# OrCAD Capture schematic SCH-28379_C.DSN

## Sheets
1 4. OpenSDA interface: size D; title: X-FRDM-KW40Z; rev: C; company: Freescale Semiconductor; note: SCH-28379 | PDF: SPF-28379; note: 6501 William Cannon Drive West; note: Austin, TX 78735-8598
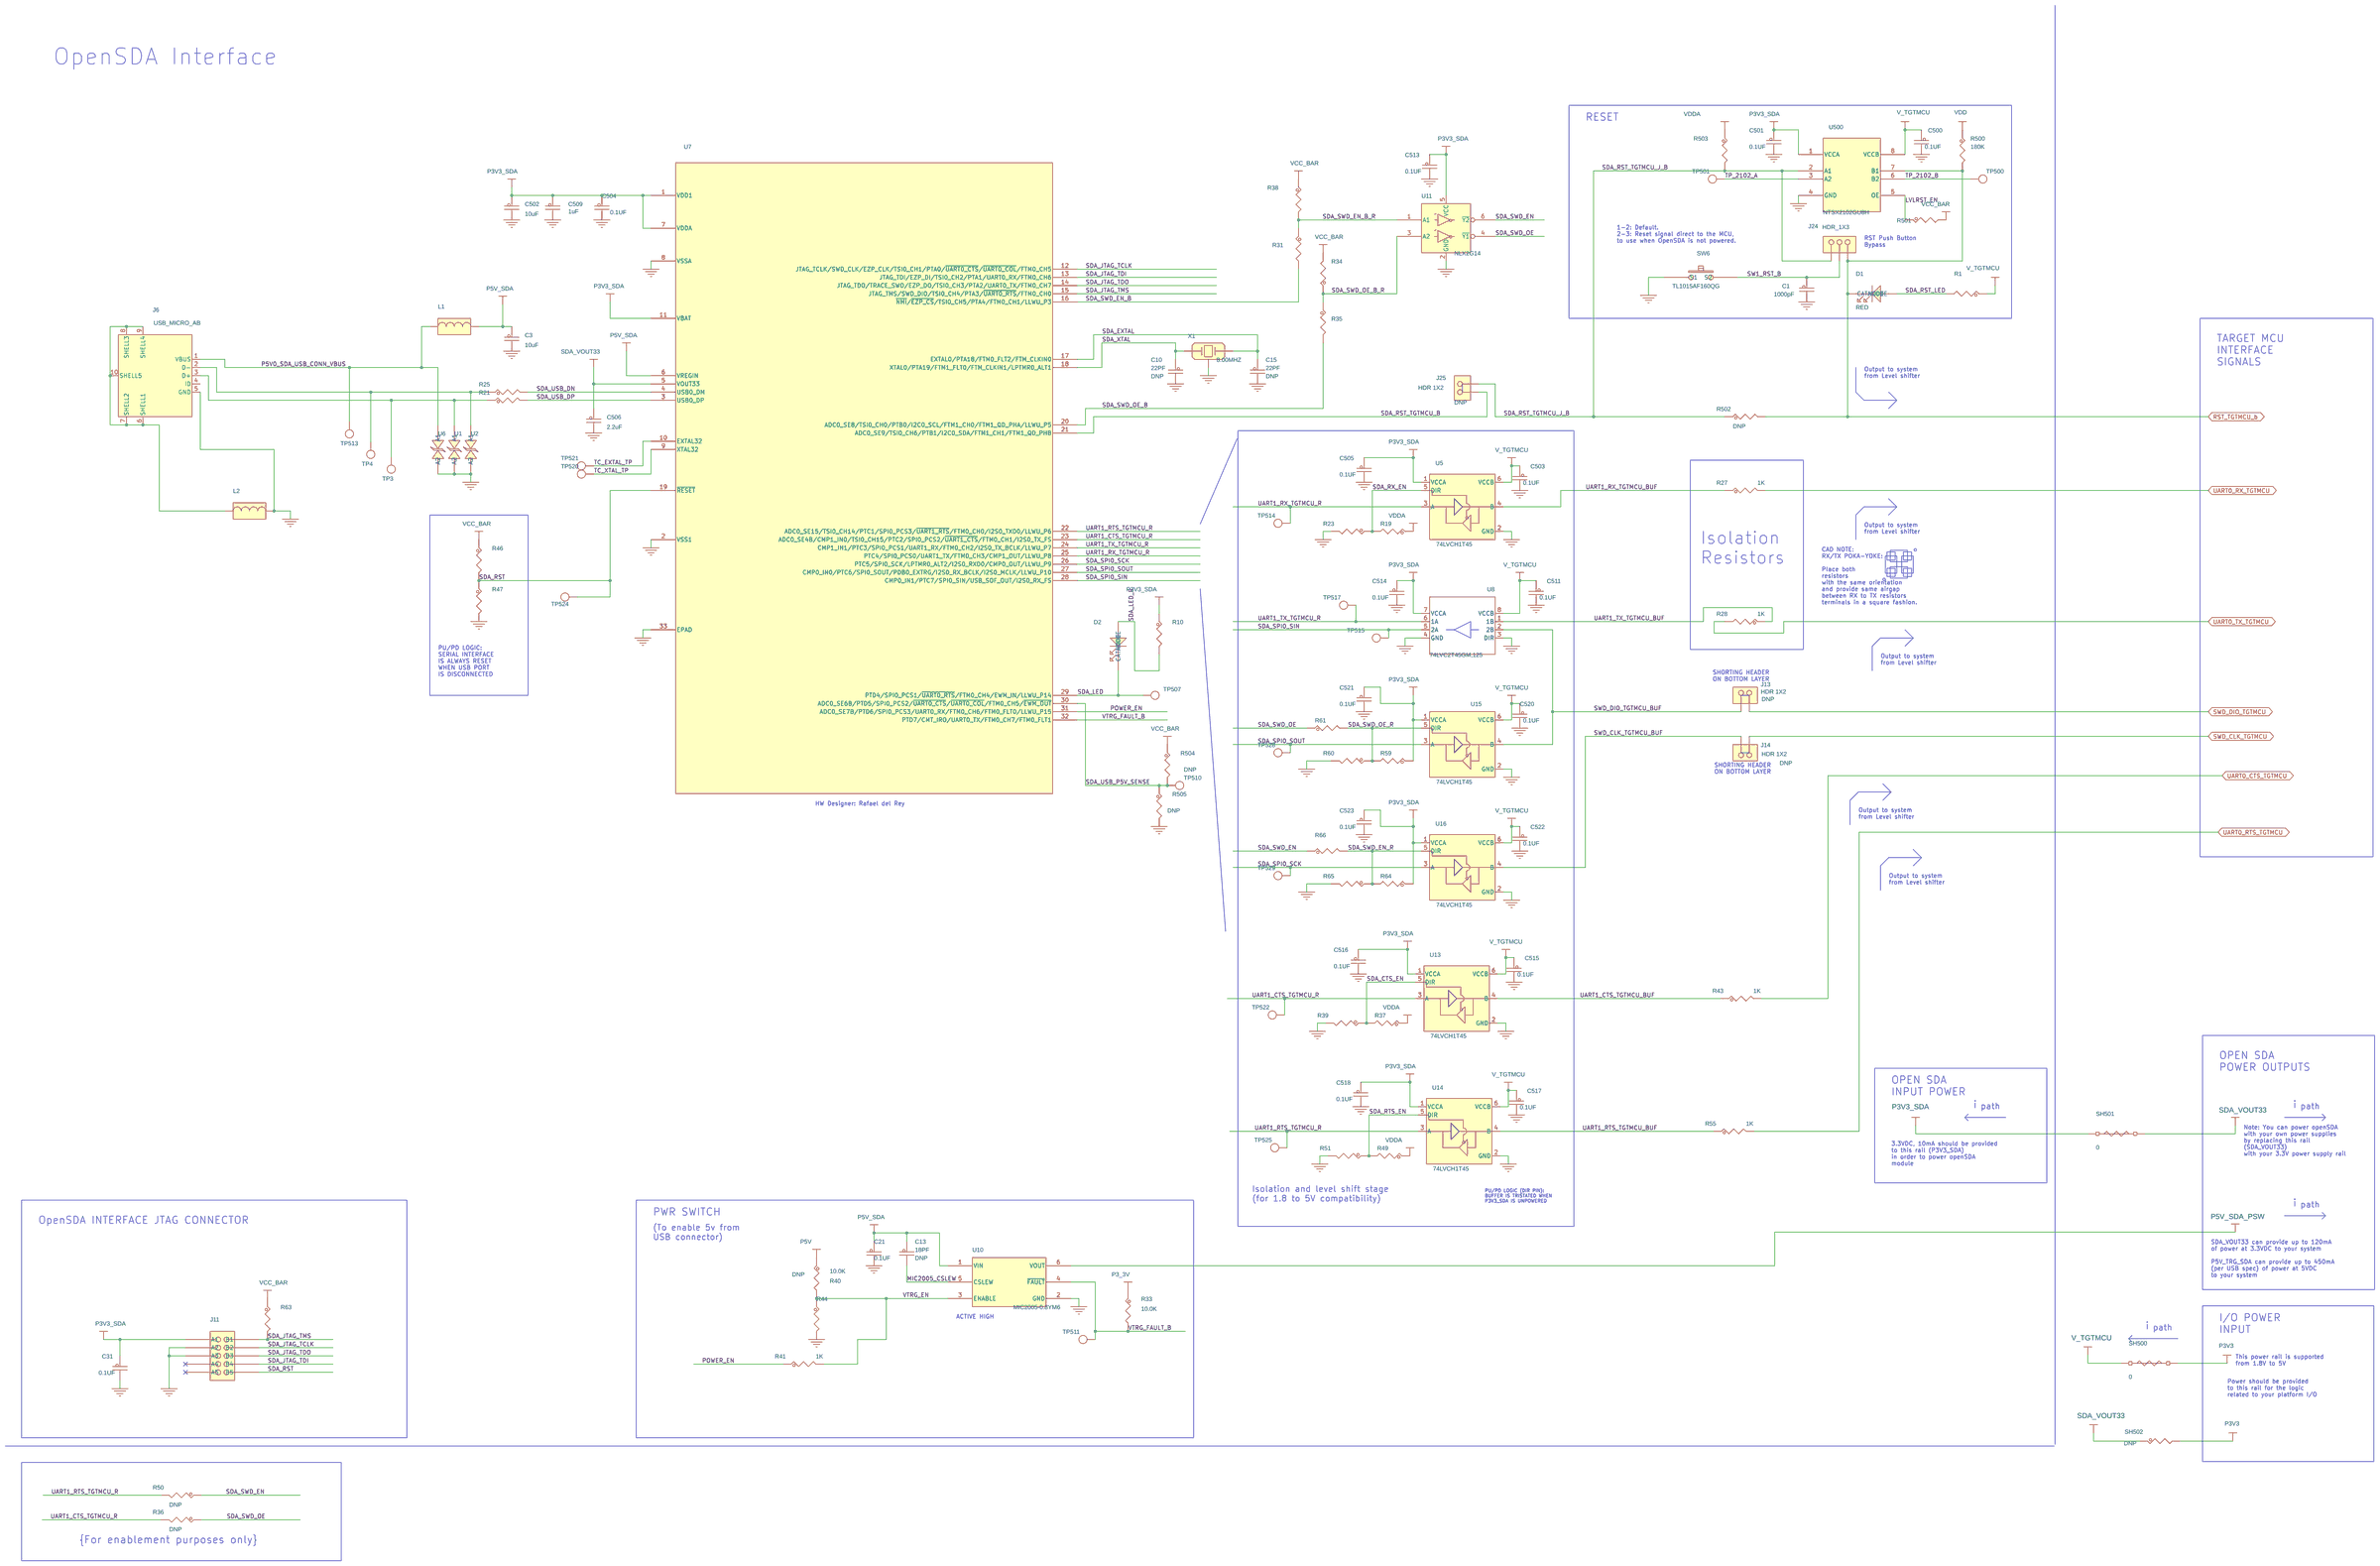
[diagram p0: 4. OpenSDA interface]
2 3. MKW40Z MCU: size C
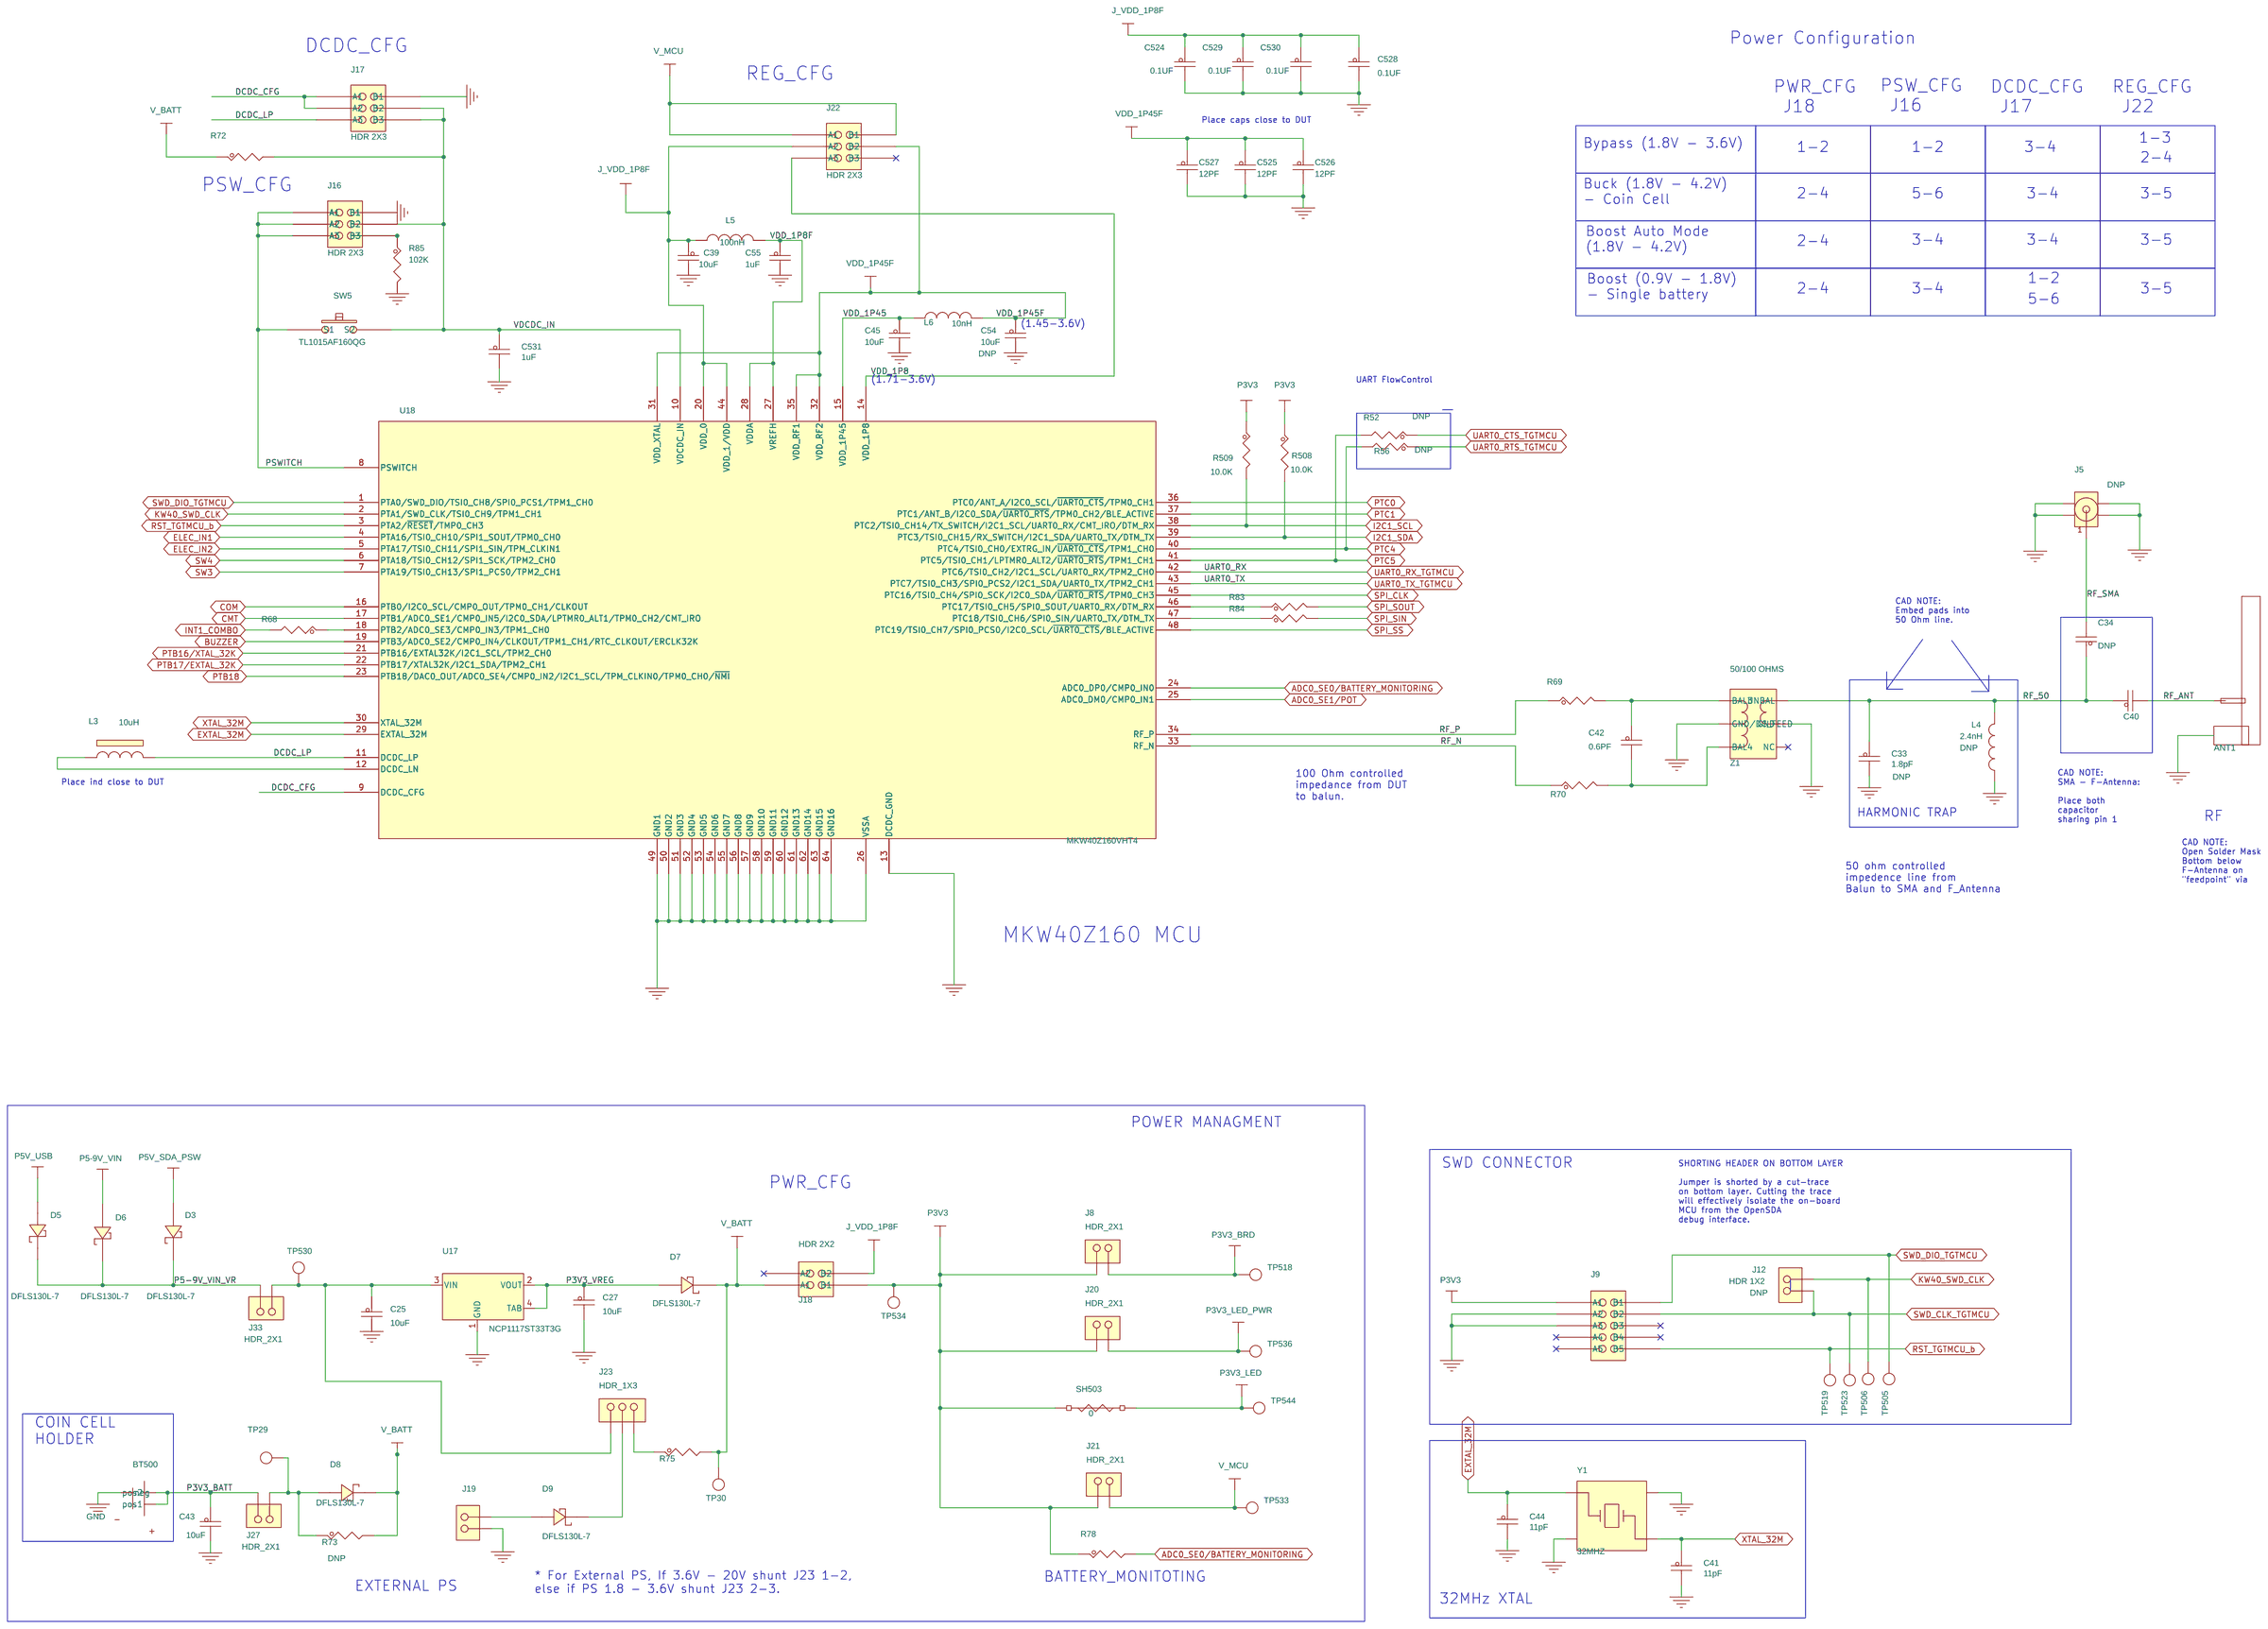
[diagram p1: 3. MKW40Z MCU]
3 2. Block Diagram
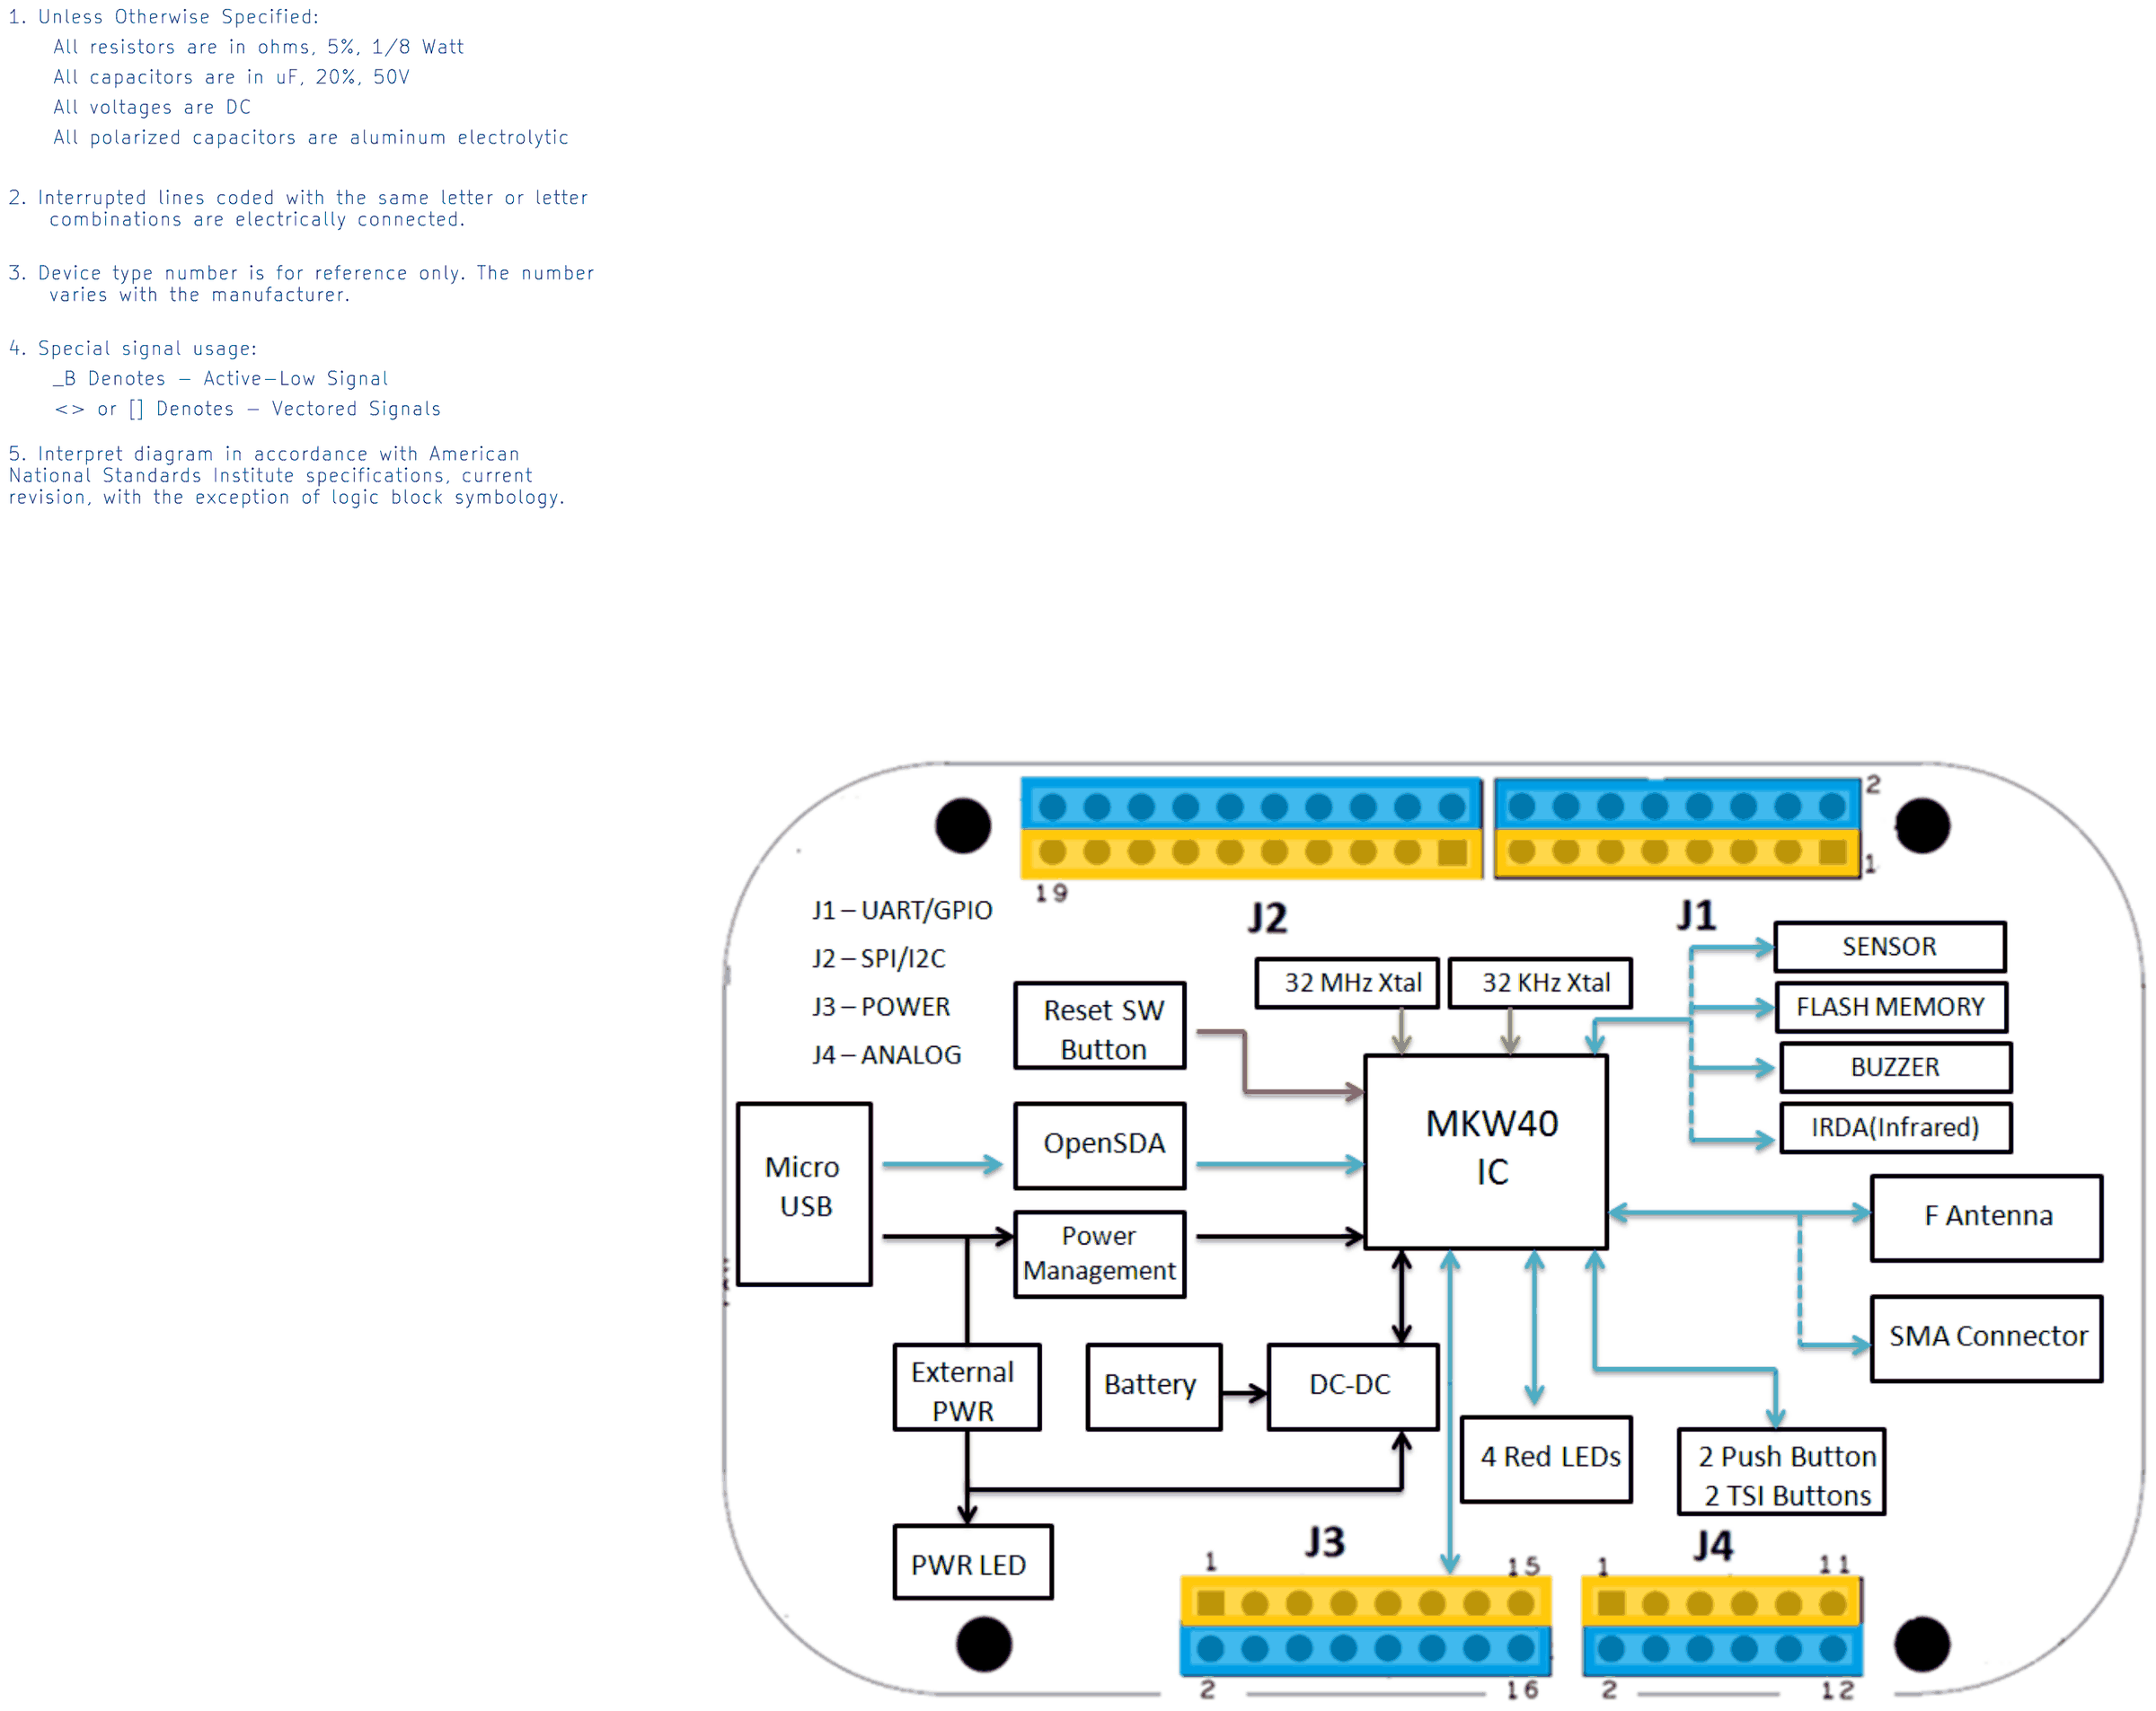
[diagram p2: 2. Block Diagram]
4 1. Title Page
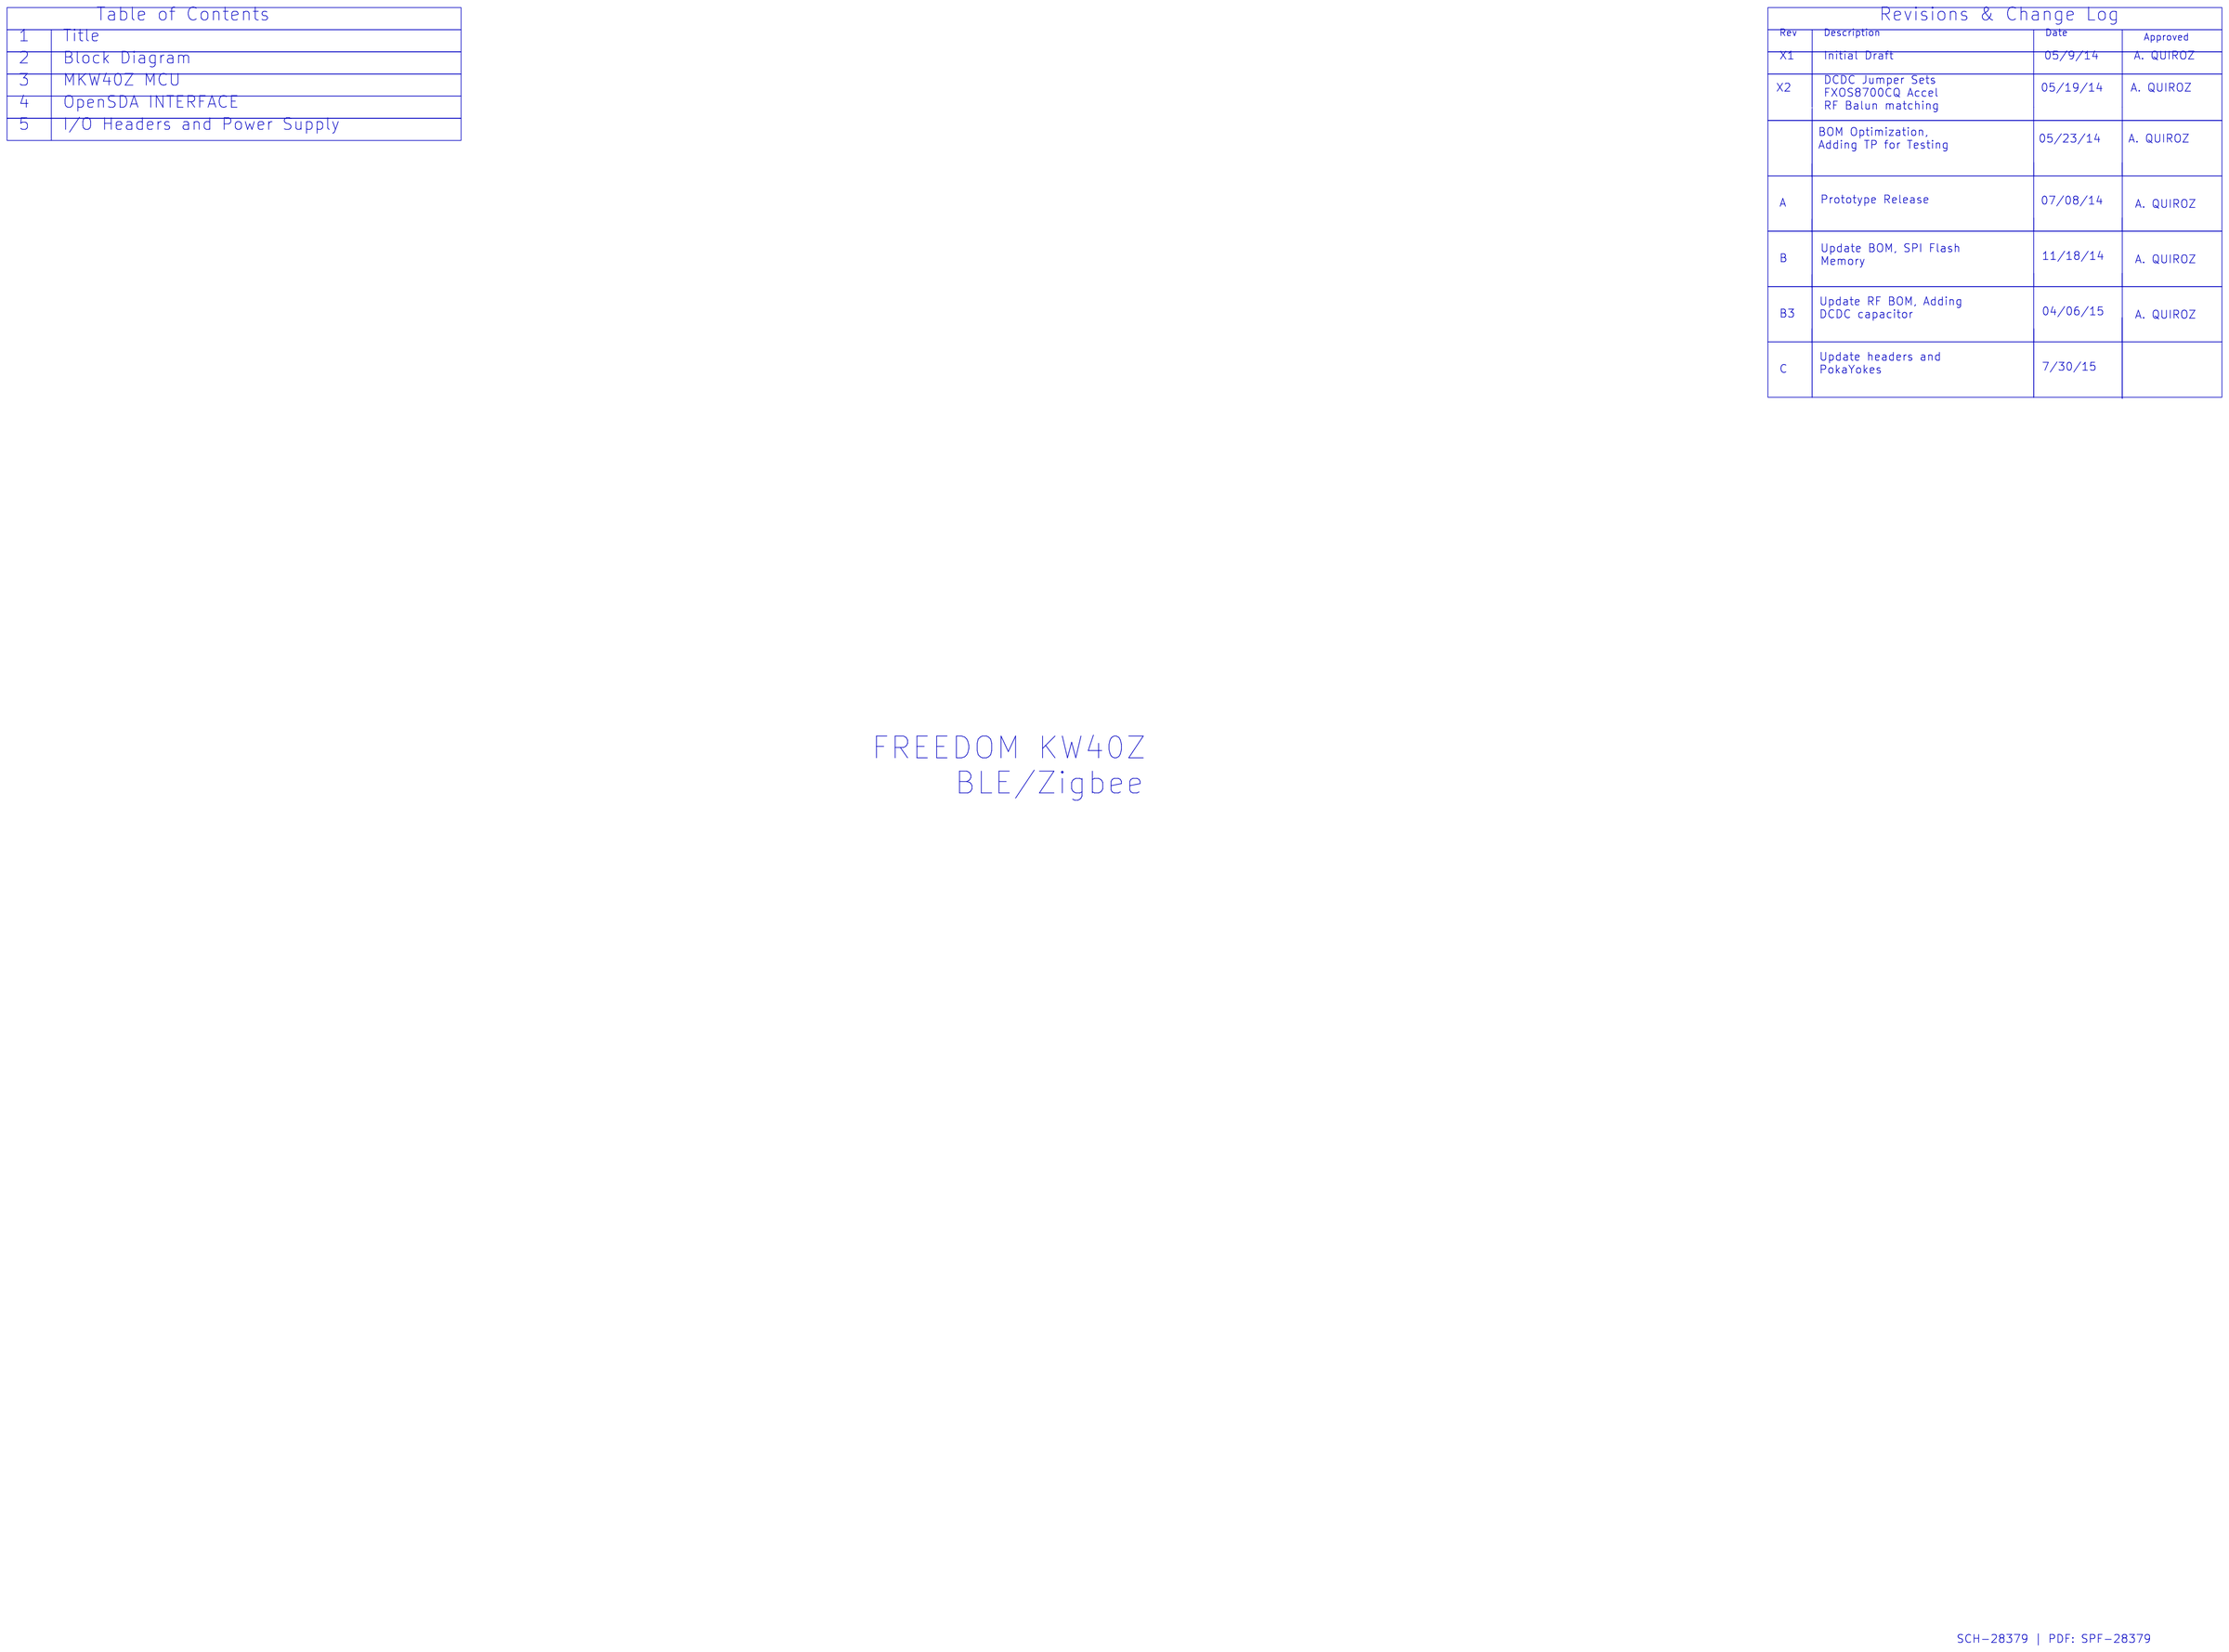
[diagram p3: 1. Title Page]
5 5. I/O Headers and Power Supply: size C
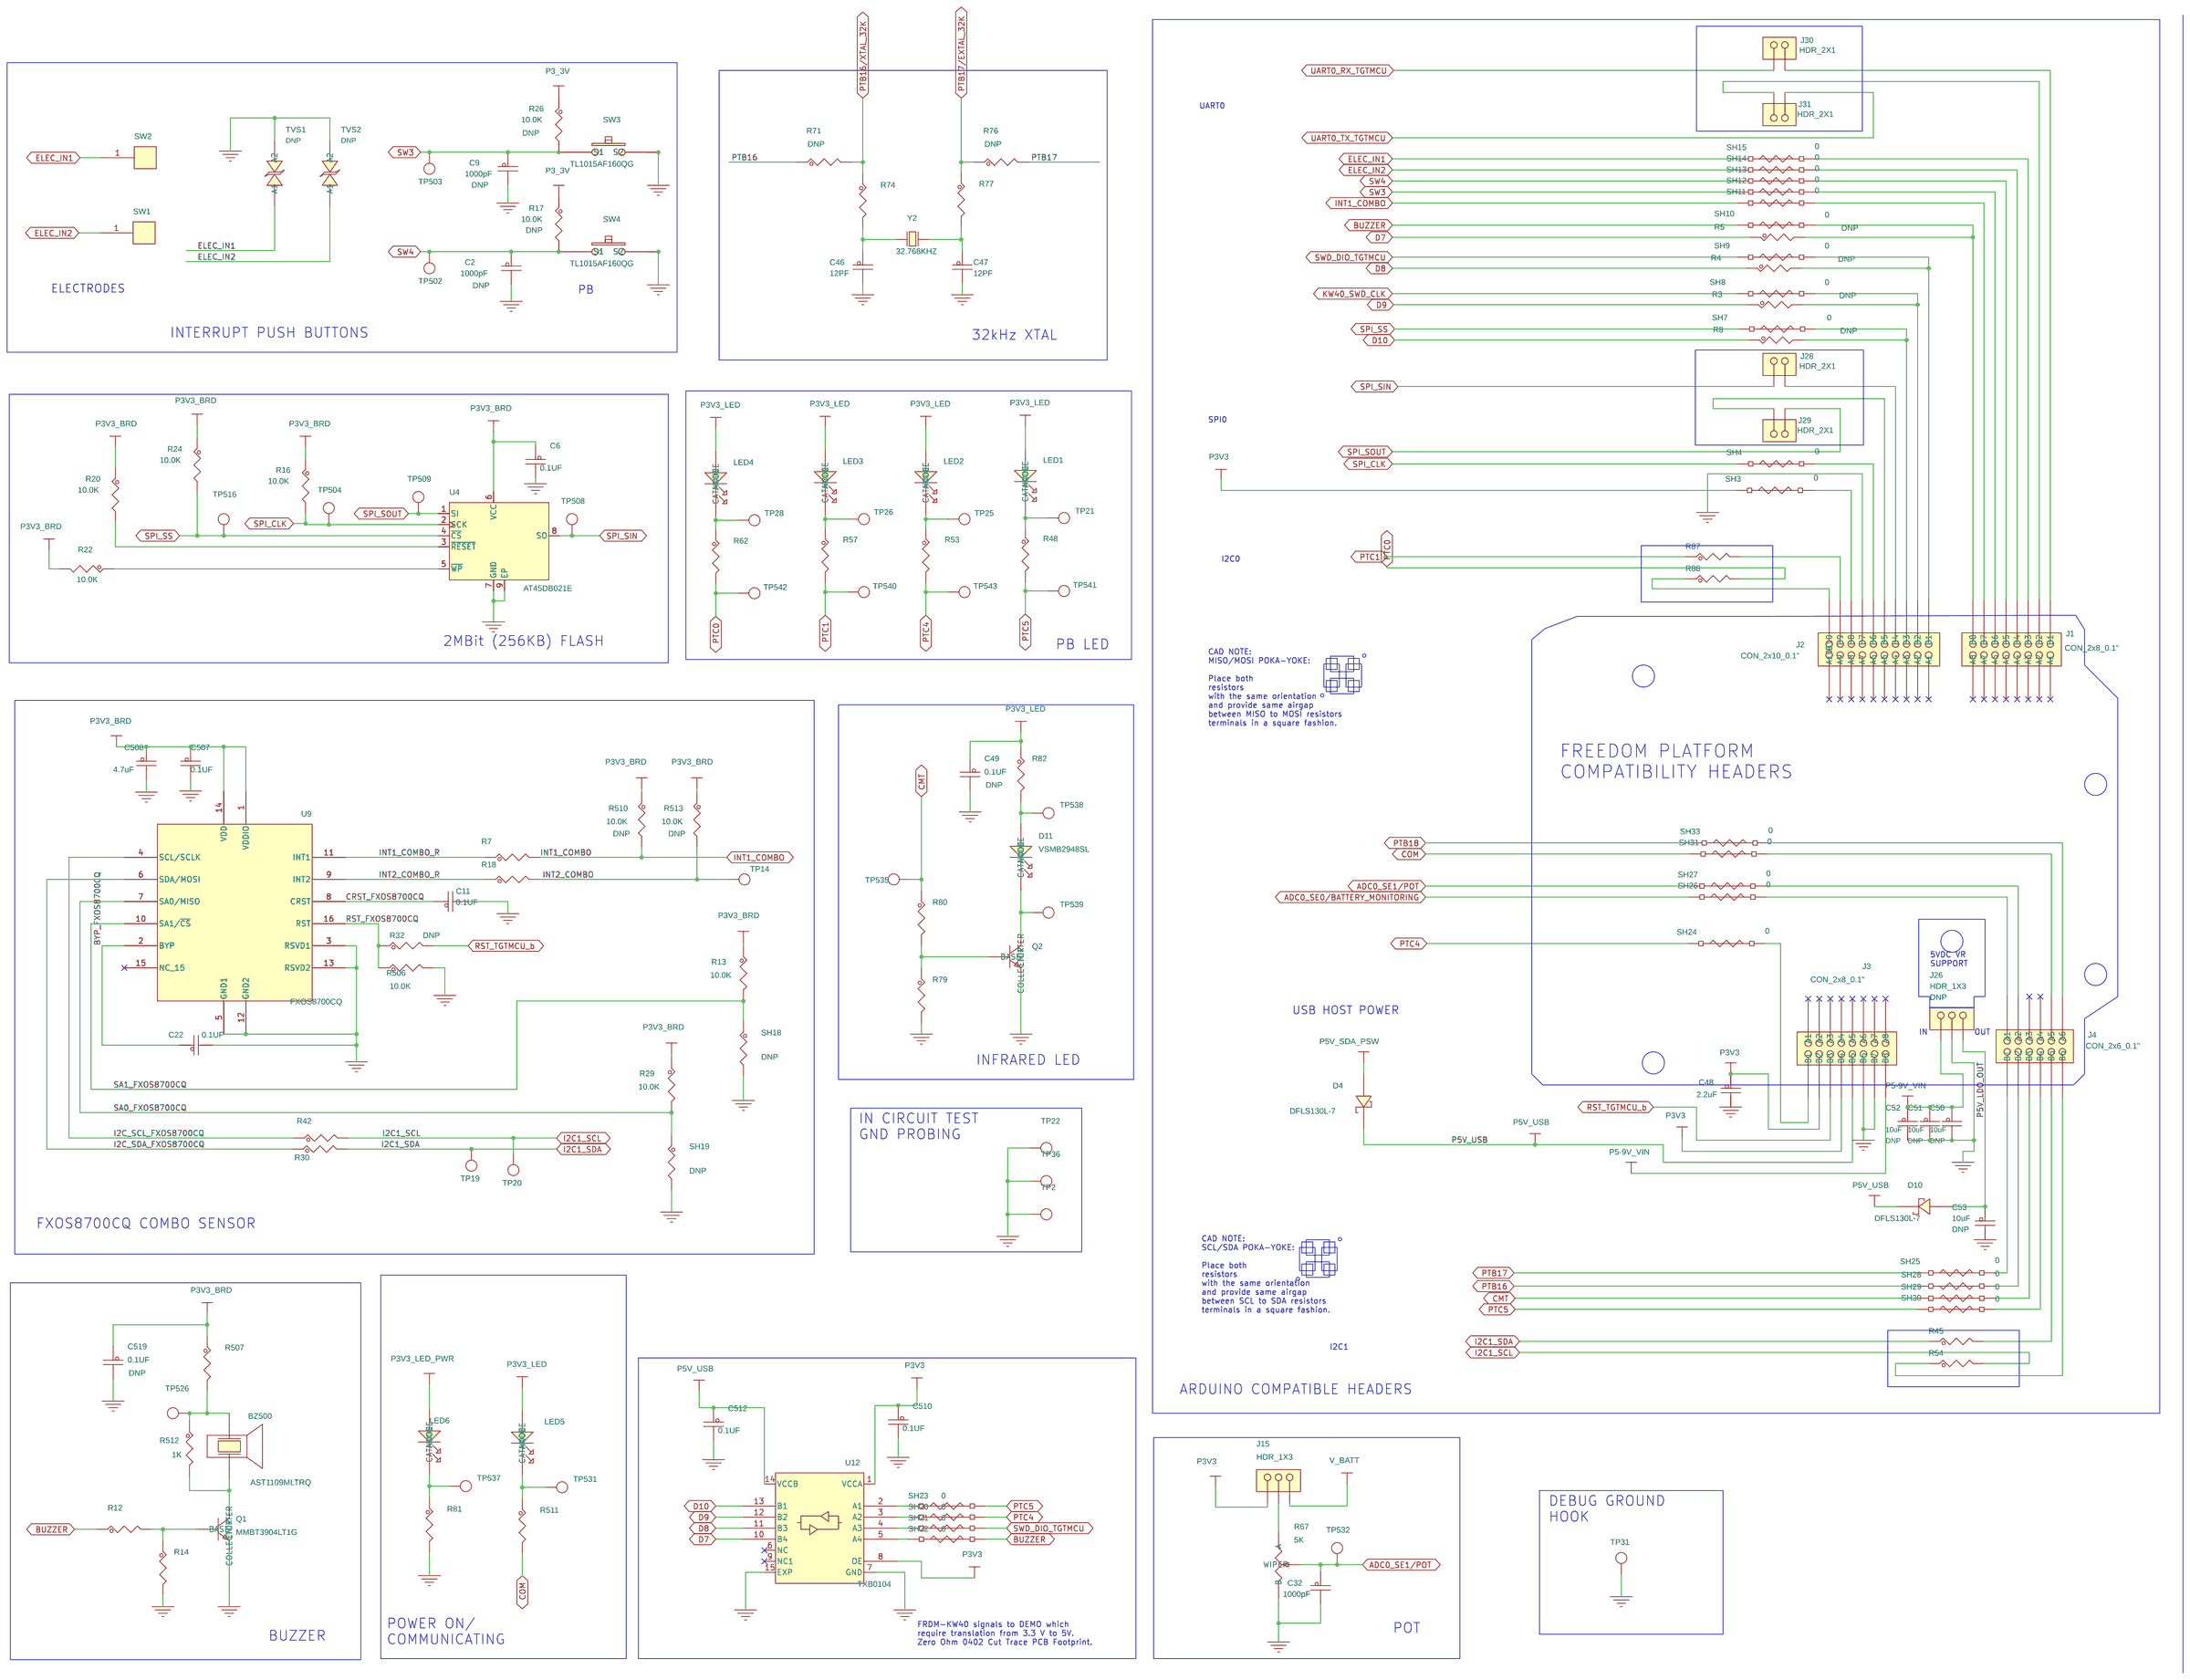
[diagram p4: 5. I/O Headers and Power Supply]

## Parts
sheet 3. MKW40Z MCU
ANT1  F_Antenna  [f_antenna_dig528-2]
BT500  3003  [batt_21x20mm]
C25  10uF  [CC0603_OV]
C27  10uF  [CC0603_OV]
C33  1.8pF  [CC0402_25]
C34  10PF  [CC0402_25]
C39  10uF  [CC0603_OV]
C40  10PF  [CC0402_25]
C41  11pF  [CC0402_25]
C42  0.6PF  [CC0402_25]
C43  10uF  [CC0603_OV]
C44  11pF  [CC0402_25]
C45  10uF  [CC0603_OV]
C54  10uF  [CC0603_OV]
C55  1uF  [CC0603_OV]
C524  0.1UF  [CC0402_25]
C525  12PF  [CC0402_25]
C526  12PF  [CC0402_25]
C527  12PF  [CC0402_25]
C528  0.1UF  [CC0402_25]
C529  0.1UF  [CC0402_25]
C530  0.1UF  [CC0402_25]
C531  1uF  [CC0402_25]
D3  DFLS130L-7  [powerdi-123_3mmx2mm]
D5  DFLS130L-7  [powerdi-123_3mmx2mm]
D6  DFLS130L-7  [powerdi-123_3mmx2mm]
D7  DFLS130L-7  [powerdi-123_3mmx2mm]
D8  DFLS130L-7  [powerdi-123_3mmx2mm]
D9  DFLS130L-7  [powerdi-123_3mmx2mm]
J5  SMA  [CON_SMA_EDGE_062]
J8  HDR_2X1  [hdr102_2mm]
J9  HDR 2X5  [hdr_5X2_ftsh_th_nsp]
J12  HDR 1X2  [sh_hdr102_2mm_bottom]
J16  HDR 2X3  [hdr203_tmm]
J17  HDR 2X3  [hdr203_tmm]
J18  HDR 2X2  [hdr202_tmm]
J19  HDR 1X2 TH  [HDR102]
J20  HDR_2X1  [hdr102_2mm]
J21  HDR_2X1  [hdr102_2mm]
J22  HDR 2X3  [hdr203_tmm]
J23  HDR_1X3  [hdr103_78mil]
J27  HDR_2X1  [hdr102_2mm]
J33  HDR_2X1  [hdr102_2mm]
L3  10uH  [ind_vls4012e]
L4  2.4nH  [IND_0402]
L5  100nH  [IND_0402]
L6  10nH  [IND_0402]
R52  0  [RC0603_OV]
R56  0  [RC0603_OV]
R68  0  [RC0402_25]
R69  0  [RC0402_25]
R70  0  [RC0402_25]
R72  0  [RC0402_25]
R73  0  [RC0402_25]
R75  0  [RC0402_25]
R78  0  [RC0402_25]
R83  0  [RC0402_25]
R84  0  [RC0402_25]
R85  102K  [RC0402_25]
R508  10.0K  [RC0402_25]
R509  10.0K  [RC0402_25]
SH503  0  [SH0603]
SW5  TL1015AF160QG  [sw2_spst_4x3_sm]
TP29  TPAD_030  [TPAD_030]
TP30  TPAD_040  [TPAD_040]
TP505  TPAD_030  [TPAD_030]
TP506  TPAD_030  [TPAD_030]
TP518  TPAD_040  [TPAD_040]
TP519  TPAD_030  [TPAD_030]
TP523  TPAD_030  [TPAD_030]
TP530  TPAD_040  [TPAD_040]
TP533  TPAD_040  [TPAD_040]
TP534  TPAD_040  [TPAD_040]
TP536  TPAD_040  [TPAD_040]
TP544  TPAD_040  [TPAD_040]
U17  NCP1117ST33T3G  [sot223]
U18  MKW40Z160VHT4  [MAPLGA64_7X7_0P5MM]
Y1  32MHZ  [xtlosc4_3p2x2p5mm_sm]
Z1  50/100 OHMS  [xfmr6_0p65_2x1]
sheet 4. OpenSDA interface
C1  1000pF  [CC0402_25]
C3  10uF  [CC0603_OV]
C10  22PF  [CC0402_25]
C13  18PF  [CC0603_OV]
C15  22PF  [CC0402_25]
C21  0.1UF  [CC0402_25]
C31  0.1UF  [CC0402_25]
C500  0.1UF  [CC0402_25]
C501  0.1UF  [CC0402_25]
C502  10uF  [CC0603_OV]
C503  0.1UF  [CC0402_25]
C504  0.1UF  [CC0402_25]
C505  0.1UF  [CC0402_25]
C506  2.2uF  [CC0603_OV]
C509  1uF  [CC0402_25]
C511  0.1UF  [CC0402_25]
C513  0.1UF  [CC0402_25]
C514  0.1UF  [CC0402_25]
C515  0.1UF  [CC0402_25]
C516  0.1UF  [CC0402_25]
C517  0.1UF  [CC0402_25]
C518  0.1UF  [CC0402_25]
C520  0.1UF  [CC0402_25]
C521  0.1UF  [CC0402_25]
C522  0.1UF  [CC0402_25]
C523  0.1UF  [CC0402_25]
D1  RED  [LED_0603]
D2  LED GREEN  [LED_0603]
J6  USB_MICRO_AB  [con_microab_10f_25_sm_ra]
J11  HDR 2X5  [hdr_5X2_ftsh_th_nsp]
J13  HDR 1X2  [sh_hdr102_2mm_bottom]
J14  HDR 1X2  [sh_hdr102_2mm_bottom]
J24  HDR_1X3  [hdr103_78mil]
J25  HDR 1X2  [sh_hdr102_2mm_bottom]
L1  330 OHM  [ind_1608]
L2  330 OHM  [ind_1608]
R1  100  [RC0402_25]
R10  220  [RC0603_OV]
R19  4.7K  [RC0402_25]
R21  33  [RC0402_25]
R23  10.0K  [RC0402_25]
R25  33  [RC0402_25]
R27  1K  [RC0402_25]
R28  1K  [RC0402_25]
R31  0  [RC0402_25]
R33  10.0K  [RC0402_25]
R34  10.0K  [RC0402_25]
R35  0  [RC0402_25]
R36  0  [RC0402_25]
R37  4.7K  [RC0402_25]
R38  10.0K  [RC0402_25]
R39  10.0K  [RC0402_25]
R40  10.0K  [RC0402_25]
R41  1K  [RC0402_25]
R43  1K  [RC0402_25]
R44  15K  [RC0402_25]
R46  4.7K  [RC0402_25]
R47  10.0K  [RC0402_25]
R49  4.7K  [RC0402_25]
R50  0  [RC0402_25]
R51  10.0K  [RC0402_25]
R55  1K  [RC0402_25]
R59  4.7K  [RC0402_25]
R60  10.0K  [RC0402_25]
R61  0  [RC0402_25]
R63  10.0K  [RC0402_25]
R64  4.7K  [RC0402_25]
R65  10.0K  [RC0402_25]
R66  0  [RC0402_25]
R500  180K  [RC0402_25]
R501  4.7K  [RC0402_25]
R502  0  [RC0402_25]
R503  10.0K  [RC0402_25]
R504  4.7K  [RC0402_25]
R505  10.0K  [RC0402_25]
SH500  0  [SH0603]
SH501  0  [SH0603]
SH502  0  [RC0402_25]
SW6  TL1015AF160QG  [sw2_spst_4x3_sm]
TP3  TPAD_040  [TPAD_040]
TP4  TPAD_040  [TPAD_040]
TP500  TPAD_030  [TPAD_030]
TP501  TPAD_030  [TPAD_030]
TP507  TPAD_040  [TPAD_040]
TP510  TPAD_030  [TPAD_030]
TP511  TPAD_030  [TPAD_030]
TP513  TPAD_040  [TPAD_040]
TP514  TPAD_030  [TPAD_030]
TP515  TPAD_030  [TPAD_030]
TP517  TPAD_030  [TPAD_030]
TP520  TPAD_030  [TPAD_030]
TP521  TPAD_030  [TPAD_030]
TP522  TPAD_030  [TPAD_030]
TP524  TPAD_040  [TPAD_040]
TP525  TPAD_030  [TPAD_030]
TP528  TPAD_030  [TPAD_030]
TP529  TPAD_030  [TPAD_030]
U1  0402ESDA-MLP  [0402_mlp]
U2  0402ESDA-MLP  [0402_mlp]
U5  74LVCH1T45  [udfn6_1x1p5mm]
U6  0402ESDA-MLP  [0402_mlp]
U7  MK20DX128VFM5  [QFN32_S142EP]
U8  74LVC2T45GM,125  [qfn8_1p6x1p6mm]
U10  MIC2005-0.8YM6  [SOT23-6_a]
U11  NLX2G14  [UDFN6_1p45x1_0p5mm]
U13  74LVCH1T45  [udfn6_1x1p5mm]
U14  74LVCH1T45  [udfn6_1x1p5mm]
U15  74LVCH1T45  [udfn6_1x1p5mm]
U16  74LVCH1T45  [udfn6_1x1p5mm]
U500  NTSX2102GU8H  [xqfn8_1p45x1p25mm]
X1  8.00MHZ  [xtal3_3p35x1p45_sm]
sheet 5. I/O Headers and Power Supply
BZ500  AST1109MLTRQ  [buzzer_9p3x11p3_smt]
C2  1000pF  [CC0402_25]
C6  0.1UF  [CC0402_25]
C9  1000pF  [CC0402_25]
C11  0.1UF  [CC0402_25]
C22  0.1UF  [CC0402_25]
C32  1000pF  [CC0402_25]
C46  12PF  [CC0402_25]
C47  12PF  [CC0402_25]
C48  2.2uF  [CC0603_OV]
C49  0.1UF  [CC0402_25]
C50  10uF  [CC0603_OV]
C51  10uF  [CC0603_OV]
C52  10uF  [CC0603_OV]
C53  10uF  [CC0603_OV]
C507  0.1UF  [CC0402_25]
C508  4.7uF  [CC0402_25]
C510  0.1UF  [CC0402_25]
C512  0.1UF  [CC0402_25]
C519  0.1UF  [CC0402_25]
D4  DFLS130L-7  [powerdi-123_3mmx2mm]
D10  DFLS130L-7  [powerdi-123_3mmx2mm]
D11  VSMB2948SL  [led_ra_2p5x2p75_sm]
J1  CON_2x8_0.1"  [MTCONN_JT254F-D180-850-208-10D]
J2  CON_2x10_0.1"  [MTCONN_JT254F-D180-850-210-10D]
J3  CON_2x8_0.1"  [MTCONN_JT254F-D180-850-208-10D]
J4  CON_2x6_0.1"  [MTCONN_JT254F-D180-850-206-10D]
J15  HDR_1X3  [hdr103_78mil]
J26  HDR_1X3  [HDR103]
J28  HDR_2X1  [hdr102_2mm]
J29  HDR_2X1  [hdr102_2mm]
J30  HDR_2X1  [hdr102_2mm]
J31  HDR_2X1  [hdr102_2mm]
LED1  RED  [led2_0805]
LED2  RED  [led2_0805]
LED3  RED  [led2_0805]
LED4  RED  [led2_0805]
LED5  BLUE  [led2_2p34_2p1x1p25]
LED6  GREEN  [led2_0805]
Q1  MMBT3904LT1G  [SOT23]
Q2  MMBT3904LT1G  [SOT23]
R3  0  [RC0402_25]
R4  0  [RC0402_25]
R5  0  [RC0402_25]
R7  0  [RC0402_25]
R8  0  [RC0402_25]
R12  4.7K  [RC0402_25]
R13  10.0K  [RC0402_25]
R14  47K  [RC0402_25]
R16  10.0K  [RC0402_25]
R17  10.0K  [RC0402_25]
R18  0  [RC0402_25]
R20  10.0K  [RC0402_25]
R22  10.0K  [RC0402_25]
R24  10.0K  [RC0402_25]
R26  10.0K  [RC0402_25]
R29  10.0K  [RC0402_25]
R30  0  [RC0402_25]
R32  0  [RC0603_OV]
R42  0  [RC0402_25]
R45  0  [RC0603_OV]
R48  330  [RC0402_25]
R53  330  [RC0402_25]
R54  0  [RC0603_OV]
R57  330  [RC0402_25]
R62  330  [RC0402_25]
R67  5K  [pot3_3352t]
R71  0  [RC0603_OV]
R74  0  [RC0402_25]
R76  0  [RC0603_OV]
R77  0  [RC0402_25]
R79  27K  [RC0402_25]
R80  1.5K  [RC0402_25]
R81  330  [RC0402_25]
R82  18.2  [RC0805_OV]
R87  0  [RC0603_OV]
R88  0  [RC0603_OV]
R506  10.0K  [RC0402_25]
R507  0  [RC0402_25]
R510  10.0K  [RC0402_25]
R511  330  [RC0402_25]
R512  1K  [RC0402_25]
R513  10.0K  [RC0402_25]
SH3  0  [SH0402]
SH4  0  [SH0402]
SH7  0  [SH0402]
SH8  0  [SH0402]
SH9  0  [SH0402]
SH10  0  [SH0402]
SH11  0  [SH0402]
SH12  0  [SH0402]
SH13  0  [SH0402]
SH14  0  [SH0402]
SH15  0  [SH0402]
SH18  0  [RC0402_25]
SH19  0  [RC0402_25]
SH20  0  [SH0402]
SH21  0  [SH0402]
SH22  0  [SH0402]
SH23  0  [SH0402]
SH24  0  [SH0402]
SH25  0  [SH0402]
SH26  0  [SH0402]
SH27  0  [SH0402]
SH28  0  [SH0402]
SH29  0  [SH0402]
SH30  0  [SH0402]
SH31  0  [SH0402]
SH33  0  [SH0402]
SW1  3x3mm  [electrode_sq_3mm]
SW2  3x3mm  [electrode_sq_3mm]
SW3  TL1015AF160QG  [sw2_spst_4x3_sm]
SW4  TL1015AF160QG  [sw2_spst_4x3_sm]
TP2  TPAD_030  [TPAD_030]
TP14  TPAD_030  [TPAD_030]
TP19  TPAD_030  [TPAD_030]
TP20  TPAD_030  [TPAD_030]
TP21  TPAD_040  [TPAD_040]
TP22  TPAD_030  [TPAD_030]
TP25  TPAD_040  [TPAD_040]
TP26  TPAD_040  [TPAD_040]
TP28  TPAD_040  [TPAD_040]
TP31  TESTLOOP_BLACK  [tp_th_063]
TP36  TPAD_030  [TPAD_030]
TP502  TPAD_030  [TPAD_030]
TP503  TPAD_030  [TPAD_030]
TP504  TPAD_030  [TPAD_030]
TP508  TPAD_030  [TPAD_030]
TP509  TPAD_030  [TPAD_030]
TP516  TPAD_030  [TPAD_030]
TP526  TPAD_030  [TPAD_030]
TP531  TPAD_040  [TPAD_040]
TP532  TPAD_030  [TPAD_030]
TP535  TPAD_040  [TPAD_040]
TP537  TPAD_040  [TPAD_040]
TP538  TPAD_040  [TPAD_040]
TP539  TPAD_040  [TPAD_040]
TP540  TPAD_030  [TPAD_030]
TP541  TPAD_030  [TPAD_030]
TP542  TPAD_030  [TPAD_030]
TP543  TPAD_030  [TPAD_030]
TVS1  PGB2010402KRHF  [diode_0402]
TVS2  PGB2010402KRHF  [diode_0402]
U4  AT45DB021E  [dfn8_1p27_6x5mm_3p6x4p2]
U9  FXOS8700CQ  [qfn5x3_0p5_3x3]
U12  TXB0104  [qfn14_rgy]
Y2  32.768KHZ  [XTAL2-3p2x1p5-SM]

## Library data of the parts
ANT1 = F_Antenna: PCB F ANTENNA, NO PART ORDER; AGILE_PN: 510-75678; CAD_APPROVED: Yes; HEIGHT: 0MM; MFG_NAME01: NOT A PART; MFG_PN01: NOT A PART; ROHS: Yes
BT500 = BATTERY_SKT_3V: HOLDER BATTERY 20MM DIA TH; AGILE_PN: 801-76130; CAD_APPROVED: Yes; HEIGHT: 4.21MM; MFG_NAME01: Keystone Electronics; ROHS: Yes
C3 C25 C27 C43 C502 = CAP_NP: CAP CER 10uF 16V 20% X5R 0603; AGILE_PN: 150-79092; CAD_APPROVED: Yes; FPLIST: CC0603_OV,CC0603,0603_CC; HEIGHT: 1mm; MFG_NAME01: TAIYO YUDEN; MFG_PN01: EMK107BBJ106MA-T; ROHS: Yes; TOL: 10%; Tolerance: 20%; VOLTAGE: 16V
C33 = CAP_NP: CAP CER 1.8PF 50V 0.25PF C0G 0402; AGILE_PN: 150-75963; ASSY_OPT: DNP; CAD_APPROVED: Yes; FPLIST: CC0402_25,CC0402_HD,0402_CC; HEIGHT: 0.55MM; MFG_NAME01: MURATA; MFG_PN01: GRM1555C1H1R8CA01D; ROHS: Yes; Tolerance: 0.25pF; VOLTAGE: 50V
C34 = CAP_NP: CAP CER 10PF 50V 5% C0G 0402; AGILE_PN: 150-75265; ASSY_OPT: DNP; CAD_APPROVED: YES; FPLIST: CC0402_25,CC0402_HD,0402_CC; HEIGHT: 0.635MM; MFG_NAME01: AVX; MFG_PN01: 04025A100JAT2A; ROHS: Yes; TOL: 5%; Tolerance: 5%; VOLTAGE: 50V
C39 C45 = CAP_NP: CAP CER 10uF 16V 20% X5R 0603; AGILE_PN: 150-79092; CAD_APPROVED: Yes; FPLIST: CC0603_OV,CC0603,0603_CC; HEIGHT: 1mm; MFG_NAME01: TAIYO YUDEN; MFG_PN01: EMK107BBJ106MA-T; ROHS: Yes; Tolerance: 20%; VOLTAGE: 16V
C40 = CAP_NP: CAP CER 10PF 50V 5% C0G 0402; AGILE_PN: 150-75265; CAD_APPROVED: YES; FPLIST: CC0402_25,CC0402_HD,0402_CC; HEIGHT: 0.635MM; MFG_NAME01: AVX; MFG_PN01: 04025A100JAT2A; ROHS: Yes; TOL: 5%; Tolerance: 5%; VOLTAGE: 50V
C41 C44 = CAP_NP: CAP CER 11pF 50V 1% C0G 0402; AGILE_PN: 150-79012; CAD_APPROVED: Yes; FPLIST: CC0402_25,CC0402_HD,0402_CC; HEIGHT: 0.6 MM; MFG_NAME01: AVX; MFG_PN01: 04025U110FAT2A; ROHS: Yes; Tolerance: 1%; VOLTAGE: 50V
C42 = CAP_NP: CAP CER 0.6PF 50V +/-0.25PF C0G 0402; CAD_APPROVED: Yes; FPLIST: CC0402_25,CC0402_HD,0402_CC; HEIGHT: 0.55MM; MFG_NAME01: MURATA; MFG_PN01: GRM1555C1HR60CZ01; ROHS: Yes; Tolerance: +/-0.25PF; VOLTAGE: 50V
C54 = CAP_NP: CAP CER 10uF 16V 20% X5R 0603; AGILE_PN: 150-79092; ASSY_OPT: DNP; CAD_APPROVED: Yes; FPLIST: CC0603_OV,CC0603,0603_CC; HEIGHT: 1mm; MFG_NAME01: TAIYO YUDEN; MFG_PN01: EMK107BBJ106MA-T; ROHS: Yes; Tolerance: 20%; VOLTAGE: 16V
C55 = CAP_NP: CAP CER 1uF 16V 10% X5R 0603; FPLIST: CC0603_OV,CC0603,0603_CC; HEIGHT: 1mm; MFG_NAME01: TAIYO YUDEN; MFG_PN01: EMK107BJ105KA-T; ROHS: Yes; Tolerance: 10%; VOLTAGE: 16V
C6 C21 C31 C500 C501 C503-C505 C510-C518 C520-C524 C528-C530 = CAP_NP: CAP CER 0.1UF 10V 10% X5R 0402; AGILE_PN: 150-75634; CAD_APPROVED: Yes; FPLIST: CC0402_25,CC0402_HD,0402_CC; HEIGHT: 0.64MM; MFG_NAME01: KEMET; MFG_PN01: C0402C104K8PAC; ROHS: Yes; TOL: 10%; Tolerance: 10%; VOLTAGE: 10V
C46 C47 C525-C527 = CAP_NP: CAP CER 12PF 50V 5% C0G 0402; AGILE_PN: 150-75680; CAD_APPROVED: Yes; FPLIST: CC0402_25,CC0402_HD,0402_CC; HEIGHT: 0.55MM; MFG_NAME01: MURATA; MFG_PN01: GRM1555C1H120JZ01D; ROHS: Yes; Tolerance: 5%; VOLTAGE: 50V
C509 C531 = CAP_NP: CAP CER 1uF 16V 10% X5R 0402; AGILE_PN: 150-78973; CAD_APPROVED: Yes; FPLIST: CC0402_25,CC0402_HD,0402_CC; HEIGHT: 0.55 MM; MFG_NAME01: TDK; MFG_PN01: C1005X5R1C105K; ROHS: Yes; Tolerance: 10%; VOLTAGE: 16V
D3-D10 = DIODE_SCHTKY: DIODE SCH 1A 30V PowerDI123; AGILE_PN: 480-78285; CAD_APPROVED: Yes; HEIGHT: 1MM; MFG_NAME01: DIODES INC; ROHS: Yes
J5 = SMB: CON, SMA, EDGE 0.062IN, 50 OHM FEMALE 18GHZ; AGILE_PN: 211-75291; ASSY_OPT: DNP; CAD_APPROVED: Yes; HEIGHT: 4.08 MM; MFG_NAME01: EMERSON NETWORK POWER CONNECTIVITY SOLUTIONS, INC; MFG_PN01: 142-0701-851; ROHS: Yes
J8 J20 J21 J27 J33 = CONN_HDR_2X1: HDR 1X2 TH 2MM SP 217H AU 110L; HEIGHT: 5.2MM; MFG_NAME01: SAMTEC; MFG_PN01: TMM-102-02-G-S
J9 J11 = CONN_HDR_5X2: HDR 2X5 TH 50MIL CTR 167H AU 91L; AGILE_PN: 210-80192; CAD_APPROVED: Yes; FPLIST: hdr_5X2_ftsh_th,hdr_5X2_ftsh_th_nsp; HEIGHT: 4.25MM; MFG_NAME01: ANYTRONIC CORPORATION LIMITED; MFG_PN01: 0922S0205011N6T-2LF; ROHS: Yes
J12 = CONN_HDR_2X1: HDR 1X2 TH 2MM SP 217H AU 110L; ASSY_OPT: DNP; CAD_APPROVED: Yes; HEIGHT: 5.2MM; MFG_NAME01: SAMTEC; MFG_PN01: TMM-102-02-G-S; ROHS: Yes
J16 J17 J22 = CONN_HDR_3X2: HDR 2X3 TH 2MM CTR 217H AU 110L; AGILE_PN: 210-77094; CAD_APPROVED: Yes; HEIGHT: 5.2MM; MFG_NAME01: SAMTEC; MFG_PN01: TMM-103-02-G-D; ROHS: Yes
J18 = CONN_HDR_2X2: HDR 2X2 TH 2MM CTR 217H AU 110L; AGILE_PN: 210-77113; CAD_APPROVED: Yes; HEIGHT: 5.2MM; MFG_NAME01: SAMTEC; MFG_PN01: TMM-102-02-G-D; ROHS: Yes
J19 = CONN_HDR_2X1: HDR 1X2 TH 100MIL SP 339H AU 98L; AGILE_PN: 210-75439; CAD_APPROVED: YES; HEIGHT: 8.71 MM; MFG_NAME01: SAMTEC; MFG_PN01: TSW-102-07-G-S; ROHS: Yes
J15 J23 J24 = CONN_HDR_3X1: HDR 1X3 TH 2MM SP 217H AU 110L; AGILE_PN: 210-77092; CAD_APPROVED: Yes; HEIGHT: 5.2MM; MFG_NAME01: SAMTEC; MFG_PN01: TMM-103-02-G-S; ROHS: Yes
L3 = IND_FERRITE: IND WW FER 10uH@1MHz 0.99A 20% 4012; AGILE_PN: 180-78215; CAD_APPROVED: Yes; HEIGHT: 1.2MM; MFG_NAME01: TDK; MFG_PN01: VLS4012ET-100M; PART_TYPE: FERRITE\BEAD; ROHS: Yes
L4 = INDUCTOR: IND -- 0.0024UH@100MHZ 300MA 0.0003UH 0402; AGILE_PN: 180-76425; ASSY_OPT: DNP; CAD_APPROVED: Yes; FPLIST: IND_0402,0402_CC; HEIGHT: 0.55mm; MFG_NAME01: MURATA; MFG_PN01: LQG15HN2N4S02D; ROHS: Yes; Tolerance: 0.0003UH
L5 = INDUCTOR: IND -- 0.1uH@100MHZ 200MA 5% 0402; FPLIST: IND_0402,0402_CC; HEIGHT: 0.6MM; MFG_NAME01: TDK; MFG_PN01: MLG1005SR10JT000; PART_TYPE: INDUCTOR\0402; ROHS: Yes; Tolerance: 5%
L6 = INDUCTOR: IND -- 0.010uH@100MHZ 350MA 5% 0402; AGILE_PN: 180-78238; CAD_APPROVED: Yes; FPLIST: IND_0402,0402_CC; HEIGHT: 0.6MM; MFG_NAME01: TDK; MFG_PN01: MLK1005S10NJT000; PART_TYPE: INDUCTOR\0402; ROHS: Yes; Tolerance: 5%
R32 R52 R56 R71 R76 = RES: RES MF ZERO OHM 1/10W -- AEC-Q200 0603; AGILE_PN: 470-75407; ASSY_OPT: DNP; CAD_APPROVED: Yes; FPLIST: RC0603_OV,RC0603,R603-X2,0603_CC; MFG_NAME01: VISHAY INTERTECHNOLOGY; MFG_PN01: CRCW06030000Z0EA; ROHS: Yes; Tolerance: 1%
R7 R18 R30 R31 R35 R42 R61 R66 R68-R70 R72 R74 R75 R77 R78 R83 R84 R507 = RES: RES MF ZERO OHM 1/16W 5% 0402; AGILE_PN: 470-75394; CAD_APPROVED: Yes; FPLIST: RC0402_25,RC0402_HD,RC0402_X2,0402_CC; MFG_NAME01: ROHM; MFG_PN01: MCR01MZPJ000; ROHS: Yes; Tolerance: 5%
R3-R5 R8 R36 R50 R73 SH18 SH19 SH502 = RES: RES MF ZERO OHM 1/16W 5% 0402; AGILE_PN: 470-75394; ASSY_OPT: DNP; CAD_APPROVED: Yes; FPLIST: RC0402_25,RC0402_HD,RC0402_X2,0402_CC; MFG_NAME01: ROHM; MFG_PN01: MCR01MZPJ000; ROHS: Yes; Tolerance: 5%
R85 = RES: RES MF 102K  1/16W 1% 0402; AGILE_PN: 470-31062; CAD_APPROVED: Yes; FPLIST: RC0402_25,RC0402_HD,0402_CC; MFG_NAME01: KOA SPEER; MFG_PN01: RK73H1ETTP1023F; ROHS: Yes; Tolerance: 1%
R13 R16 R20 R22 R24 R29 R506 R508 R509 = RES: RES MF 10.0K 1/16W 1% AEC-Q200 0402; AGILE_PN: 470-75416; CAD_APPROVED: Yes; FPLIST: RC0402_25,RC0402_HD,0402_CC; HEIGHT: 0.4MM; MFG_NAME01: VISHAY INTERTECHNOLOGY; MFG_PN01: CRCW040210K0FKED; PRIORITY_PN: 006-00552; ROHS: Yes; TOL: 1%; Tolerance: 1%
SH500 SH501 SH503 = RES_SHORT-2: ZERO OHM CUT TRACE 0603 PADS; NO PART TO ORDER; AGILE_PN: 470-80018; CAD_APPROVED: Yes; FPLIST: SH0603,SH0603_CC,SH0603-X2_PIN1TO2,SH0603-X2_PIN2TO3; MFG_NAME01: LAYOUT ELEMENT ONLY; MFG_PN01: LAYOUT ELEMENT ONLY; ROHS: Yes
SW3-SW6 = SW_SPNO_2P: SW SPST PB 50MA 12V SMT; AGILE_PN: 510-77720; CAD_APPROVED: Yes; HEIGHT: 2.25MM; MFG_NAME01: E SWITCH; ROHS: Yes
TP2 TP14 TP19 TP20 TP22 TP29 TP36 TP500-TP506 TP508-TP511 TP514-TP517 TP519-TP523 TP525 TP526 TP528 TP529 TP532 = TESTLOOP: TEST POINT PAD 30MIL DIA SMT, NO PART TO ORDER; AGILE_PN: 211-76642; CAD_APPROVED: Yes; HEIGHT: 0.1MM; MFG_NAME01: NOTACOMPONENT; MFG_PN01: NOTACOMPONENT; ROHS: Yes
TP3 TP4 TP21 TP25 TP26 TP28 TP30 TP507 TP513 TP518 TP524 TP530 TP531 TP533-TP539 TP544 = TestLoop: TEST POINT PAD 40MIL DIA SMT, NO PART TO ORDER; AGILE_PN: 211-76643; CAD_APPROVED: Yes; HEIGHT: 0.1MM; MFG_NAME01: NOTACOMPONENT; MFG_PN01: NOTACOMPONENT; ROHS: Yes
U17 = LD1117AS18: IC VREG LDO 1A 3.3V SOT223; AGILE_PN: 312-80039; CAD_APPROVED: Yes; HEIGHT: 1.8MM; MFG_NAME01: ON Semiconductor; ROHS: Yes
U18 = MKW40Z160_MAPLGA64: IC MCU XCVR 2.4GHZ BLUETOOTH LOW ENERGY MAPLGA64; AGILE_PN: 344-02058; CAD_APPROVED: Yes; HEIGHT: 0.98 MM; MFG_NAME01: FREESCALE SEMICONDUCTOR; ROHS: Yes
Y1 = XTAL_13Y: XTAL 32MHZ 9PF -- SMT 3.2X2.5MM; AGILE_PN: 230-77690; CAD_APPROVED: Yes; HEIGHT: 0.8MM; MFG_NAME01: NDK; MFG_PN01: EXS00A-CS02368; ROHS: Yes
Z1 = 2450BL: XFMR BALUN 2.45GHZ +/-50MHZ 50/100OHM 3W SMT; AGILE_PN: 560-75614; CAD_APPROVED: Yes; FPLIST: xfmr6_0p65_2x1,XFMR_HHM1525_2x1_25mm_6P; HEIGHT: 1.05MM; MFG_NAME01: JOHANSON TECHNOLOGY; MFG_PN01: 2450BL15B100_; PART_TYPE: TRANSFORMERS\RF; ROHS: Yes
C1 C32 = CAP_NP: CAP CER 1000PF 50V 5% C0G 0402; AGILE_PN: 150-76334; CAD_APPROVED: Yes; FPLIST: CC0402_25,CC0402_HD,0402_CC; HEIGHT: 0.55MM; MFG_NAME01: MURATA; MFG_PN01: GRM1555C1H102JA01D; ROHS: Yes; Tolerance: 5%; VOLTAGE: 50V
C10 C15 = CAP_NP: CAP CER 22PF 50V 5% C0G 0402; AGILE_PN: 150-75266; ASSY_OPT: DNP; CAD_APPROVED: Yes; FPLIST: CC0402_25,CC0402_HD,0402_CC; HEIGHT: 0.635MM; MFG_NAME01: AVX; MFG_PN01: 04025A220JAT2A; ROHS: Yes; Tolerance: 5%; VOLTAGE: 50V
C13 = CAP_NP: CAP CER 18PF 50V 5% C0G 0603; AGILE_PN: 150-75116; ASSY_OPT: DNP; CAD_APPROVED: Yes; FPLIST: CC0603_OV,CC0603,0603_CC; HEIGHT: 0.90MM; MFG_NAME01: YAGEO AMERICA; MFG_PN01: CC0603JRNPO9BN180; ROHS: Yes; TOL: 5%; Tolerance: 5%; VOLTAGE: 50V
C48 C506 = CAP_NP: CAP CER 2.2uF 25V 10% X5R 0603; AGILE_PN: 150-78975; CAD_APPROVED: Yes; FPLIST: CC0603_OV,CC0603,0603_CC; HEIGHT: 0.9 MM; MFG_NAME01: TDK; MFG_PN01: C1608X5R1E225K; ROHS: Yes; Tolerance: 10%; VOLTAGE: 25V
D1 = LED: LED ULTRA BRIGHT RED SGL 30MA 0603; AGILE_PN: 370-75079; CAD_APPROVED: Yes; HEIGHT: 0.9MM; MFG_NAME01: LITE ON; MFG_PN01: LTST-C190KRKT; ROHS: Yes
D2 = LED: LED GRN SGL 20MA 0603; AGILE_PN: 370-76565; CAD_APPROVED: Yes; HEIGHT: 0.67MM; MFG_NAME01: osram; MFG_PN01: LG L29K-G2J1-24-Z; ROHS: Yes
J6 = MICRO_USB_CONN_10PIN: CON 5 USB_MICRO_AB_RECEPTACLE RA SKT SMT 0.65MM SP 122H AU; AGILE_PN: 211-78945; CAD_APPROVED: Yes; HEIGHT: 3.1MM; MFG_NAME01: molex; MFG_PN01: 0475900001; ROHS: Yes
J13 J14 J25 = CONN_HDR_2X1: HDR 1X2 TH 2MM SP 217H AU 110L, NO PART TO ORDER; AGILE_PN: 210-80699; ASSY_OPT: DNP; CAD_APPROVED: Yes; HEIGHT: 5.2MM; MFG_NAME01: N/A; MFG_PN01: No part to order; ROHS: Yes
L1 L2 = BEAD: IND FER BEAD 330OHM@100MHZ 1.7A 0603; AGILE_PN: 180-78156; CAD_APPROVED: Yes; FPLIST: ind_1608,0603_CC; HEIGHT: 0.95MM; MFG_NAME01: TDK; MFG_PN01: MPZ1608S331A; PART_TYPE: FERRITE\BEAD; ROHS: Yes; Tolerance: 25%
R1 = RES: RES MF 100 OHM 1/16W 5% 0402; AGILE_PN: 470-75591; CAD_APPROVED: Yes; FPLIST: RC0402_25,RC0402_HD,RC0402_X2,0402_CC; HEIGHT: 0.55 MM; MFG_NAME01: VENKEL COMPANY; MFG_PN01: CR040216W101JT; ROHS: Yes; TOL: 1%; Tolerance: 5%
R10 = RES: RES MF 220 OHM 1/10W 5% 0603; AGILE_PN: 470-30297; CAD_APPROVED: Yes; FPLIST: RC0603_OV,RC0603,0603_CC; MFG_NAME01: KOA SPEER; MFG_PN01: RK73B1JTTD221J; ROHS: Yes; Tolerance: 5%
R19 R37 R46 R49 R59 R64 R501 = RES: RES MF 4.7K 1/16W 5% 0402; AGILE_PN: 470-75626; CAD_APPROVED: Yes; FPLIST: RC0402_25,RC0402_HD,0402_CC; HEIGHT: 0.55 MM; MFG_NAME01: YAGEO AMERICA; MFG_PN01: RC0402JR-074K7L; ROHS: Yes; TOL: 1%; Tolerance: 5%
R21 R25 = RES: RES MF 33.0 OHM 1/16W 1% 0402; AGILE_PN: 470-75790; CAD_APPROVED: Yes; FPLIST: RC0402_25,RC0402_HD,RC0402_X2,0402_CC; MFG_NAME01: THYE MING TECH CO LTD; MFG_PN01: CR-02FL6---33R; ROHS: Yes; Tolerance: 1%
R23 R34 R38 R39 R51 R60 R65 R503 = RES: RES MF 10.0K 1/16W 1% AEC-Q200 0402; AGILE_PN: 470-75416; CAD_APPROVED: Yes; FPLIST: RC0402_25,RC0402_HD,0402_CC; HEIGHT: 0.55MM; MFG_NAME01: VISHAY INTERTECHNOLOGY; MFG_PN01: CRCW040210K0FKED; ROHS: Yes; TOL: 5%; Tolerance: 1%
R27 R28 R41 R43 R55 R512 = RES: RES MF 1.0K 1/16W 5% 0402; AGILE_PN: 470-75555; CAD_APPROVED: Yes; FPLIST: RC0402_25,RC0402_HD,RC0402_X2,0402_CC; MFG_NAME01: VISHAY INTERTECHNOLOGY; MFG_PN01: CRCW04021K00JNED; ROHS: Yes; Tolerance: 5%
R33 = RES: RES MF 10.0K 1/16W 1% AEC-Q200 0402; AGILE_PN: 470-75416; CAD_APPROVED: Yes; FPLIST: RC0402_25,RC0402_HD,0402_CC; HEIGHT: 0.4MM; MFG_NAME01: VISHAY INTERTECHNOLOGY; MFG_PN01: CRCW040210K0FKED; ROHS: Yes; TOL: 1%; Tolerance: 1%
R40 = RES: RES MF 10.0K 1/16W 1% AEC-Q200 0402; AGILE_PN: 470-75416; ASSY_OPT: DNP; CAD_APPROVED: Yes; FPLIST: RC0402_25,RC0402_HD,0402_CC; HEIGHT: 0.4MM; MFG_NAME01: VISHAY INTERTECHNOLOGY; MFG_PN01: CRCW040210K0FKED; ROHS: Yes; TOL: 1%; Tolerance: 1%
R44 = RES: RES MF 15K  1/16W 1% 0402; AGILE_PN: 470-30965; CAD_APPROVED: Yes; FPLIST: RC0402_25,RC0402_HD,0402_CC; HEIGHT: 0.4 MM; MFG_NAME01: KOA SPEER; MFG_PN01: RK73H1ETTP1502F; ROHS: Yes; TOL: 1%; Tolerance: 1%
R47 R63 = RES: RES MF 10.0K 1/16W 1% AEC-Q200 0402; AGILE_PN: 470-75416; CAD_APPROVED: Yes; FPLIST: RC0402_25,RC0402_HD,0402_CC; MFG_NAME01: VISHAY INTERTECHNOLOGY; MFG_PN01: CRCW040210K0FKED; ROHS: Yes; Tolerance: 1%
R500 = RES: RES MF 180K  1/16W 1% 0402; AGILE_PN: 470-31088; CAD_APPROVED: Yes; FPLIST: RC0402_25,RC0402_HD,0402_CC; MFG_NAME01: KOA SPEER; MFG_PN01: RK73H1ETTP1803F; ROHS: Yes; Tolerance: 1%
R502 = RES: RES MF ZERO OHM 1/16W 5% 0402; AGILE_PN: 470-75394; ASSY_OPT: DNP; CAD_APPROVED: Yes; FPLIST: RC0402_25,RC0402_HD,RC0402_X2,0402_CC; HEIGHT: 0.45 MM; MFG_NAME01: ROHM; MFG_PN01: MCR01MZPJ000; ROHS: Yes; TOL: 5%; Tolerance: 5%
R504 = RES: RES MF 4.7K 1/16W 5% 0402; AGILE_PN: 470-75626; ASSY_OPT: DNP; CAD_APPROVED: Yes; FPLIST: RC0402_25,RC0402_HD,0402_CC; HEIGHT: 0.55 MM; MFG_NAME01: YAGEO AMERICA; MFG_PN01: RC0402JR-074K7L; ROHS: Yes; TOL: 1%; Tolerance: 5%
R505 = RES: RES MF 10.0K 1/16W 1% AEC-Q200 0402; AGILE_PN: 470-75416; ASSY_OPT: DNP; CAD_APPROVED: Yes; FPLIST: RC0402_25,RC0402_HD,0402_CC; MFG_NAME01: VISHAY INTERTECHNOLOGY; MFG_PN01: CRCW040210K0FKED; ROHS: Yes; Tolerance: 1%
U1 U2 U6 = DIODE_TVS_BIDIR: DIODE TVS BIDIR -- 30V 0402; AGILE_PN: 480-76179; CAD_APPROVED: Yes; HEIGHT: 0.44MM; MFG_NAME01: COOPER BUSSMANN; MFG_PN01: 0402ESDA-MLP1; ROHS: Yes
U5 U13-U16 = 74LVCH1T45_6P: IC XCVR 1BIT 3-STATE DUAL 1.2-5.5V XSON6; AGILE_PN: 312-80758; CAD_APPROVED: Yes; HEIGHT: 0.5MM; MFG_NAME01: NXP SEMICONDUCTORS; MFG_PN01: 74LVCH1T45GM,132; ROHS: Yes
U7 = PK20DX128V_QFN_32P: IC MCU FLASH 128KB 50MHZ 1.71-3.6V QFN32; AGILE_PN: 344-01231; CAD_APPROVED: Yes; HEIGHT: 1MM; MFG_NAME01: FREESCALE SEMICONDUCTOR; ROHS: Yes
U8 = 74LVC2T45GM_8P: IC XCVR DUAL SUPPLY 1.2 -5.5V XQFN8; AGILE_PN: 312-80762; CAD_APPROVED: Yes; HEIGHT: 0.5MM; MFG_NAME01: NXP Semiconductors; ROHS: Yes
U10 = MIC2005-0.8YM6: IC LIN SW PWR 0.8A 2.5-5.5V SOT23-6; AGILE_PN: 315-79199; CAD_APPROVED: Yes; HEIGHT: 1.45MM; MFG_NAME01: MICREL; ROHS: Yes
U11 = NLU2GU04: IC INV DUAL SCHMITT TRIGGER 1.65-5.5V UDFN6; HEIGHT: 0.4MM; MFG_NAME01: On Semiconductor; MFG_PN01: NLX2G14AMUTCG; ROHS: Yes; VOLTAGE: 1.65-5.5V
U500 = NTSX2102GU8H_8P: IC DUAL SUPPLY XCVR 50 MBPS 5.5V XQFN8; AGILE_PN: 312-80763; CAD_APPROVED: Yes; HEIGHT: 0.5MM; MFG_NAME01: NXP Semiconductors; ROHS: Yes
X1 = XTAL_CS: XTAL 8.00MHZ RSN CERAMIC -- SMT; AGILE_PN: 230-77664; CAD_APPROVED: Yes; HEIGHT: 0.8MM; MFG_NAME01: MURATA; MFG_PN01: CSTCE8M00G55-R0; ROHS: Yes
BZ500 = BUZZER_PIEZO: AUDIO DEVICE BZR PIEZO 4.1KHZ 73DB 1-20V SMT; AGILE_PN: 510-77940; CAD_APPROVED: Yes; HEIGHT: 2 MM; MFG_NAME01: MALLORY; ROHS: Yes
C2 C9 = CAP_NP: CAP CER 1000PF 50V 5% C0G 0402; AGILE_PN: 150-76334; ASSY_OPT: DNP; CAD_APPROVED: Yes; FPLIST: CC0402_25,CC0402_HD,0402_CC; HEIGHT: 0.55MM; MFG_NAME01: MURATA; MFG_PN01: GRM1555C1H102JA01D; ROHS: Yes; Tolerance: 5%; VOLTAGE: 50V
C11 C22 C507 = CAP_NP: CAP CER 0.1UF 10V 10% X5R 0402; AGILE_PN: 150-75634; CAD_APPROVED: Yes; FPLIST: CC0402_25,CC0402_HD,0402_CC; HEIGHT: 0.64MM; MFG_NAME01: KEMET; MFG_PN01: C0402C104K8PAC; ROHS: Yes; Tolerance: 10%; VOLTAGE: 10V
C49 C519 = CAP_NP: CAP CER 0.1UF 10V 10% X5R 0402; AGILE_PN: 150-75634; ASSY_OPT: DNP; CAD_APPROVED: Yes; FPLIST: CC0402_25,CC0402_HD,0402_CC; HEIGHT: 0.64MM; MFG_NAME01: KEMET; MFG_PN01: C0402C104K8PAC; ROHS: Yes; TOL: 10%; Tolerance: 10%; VOLTAGE: 10V
C50-C53 = CAP_NP: CAP CER 10UF 16V 20% X5R 0603; AGILE_PN: 150-79092; ASSY_OPT: DNP; CAD_APPROVED: Yes; FPLIST: CC0603_OV,CC0603,0603_CC; HEIGHT: 1.016MM; MFG_NAME01: TAIYO YUDEN; MFG_PN01: EMK107BBJ106MA-T; ROHS: Yes; VOLTAGE: 10V
C508 = CAP_NP: CAP CER 4.7UF 6.3V 20% X5R 0402; AGILE_PN: 150-78463; CAD_APPROVED: Yes; FPLIST: CC0402_25,CC0402_HD,0402_CC; HEIGHT: 0.65MM; MFG_NAME01: VENKEL COMPANY; MFG_PN01: C0402X5R6R3-475MNP; ROHS: Yes; Tolerance: 20%; VOLTAGE: 6.3V
D11 = LED: LED IR RA 100mA 1.35V 940NM SMD; AGILE_PN: 370-76645; CAD_APPROVED: Yes; HEIGHT: 2.5MM; MFG_NAME01: VISHAY INTERTECHNOLOGY; ROHS: Yes
J1 J3 = CONN_2x8_MTCONN
J2 = CONN_2x10_MTCONN
J4 = CONN_2x6_MTCONN
J26 = CONN_HDR_3X1: HDR 1X3 TH 100MIL SP 330H AU 98L; AGILE_PN: 210-75442; ASSY_OPT: DNP; CAD_APPROVED: Yes; HEIGHT: 8.38 MM; MFG_NAME01: SAMTEC; MFG_PN01: HTSW-103-07-S-S; ROHS: Yes
J28-J31 = CONN_HDR_2X1: HDR 1X2 TH 2MM SP 217H AU 110L; CAD_APPROVED: Yes; HEIGHT: 5.2MM; MFG_NAME01: SAMTEC; MFG_PN01: TMM-102-02-G-S; ROHS: Yes
LED1-LED4 = LED: LED RED CLEAR SGL 30MA SMT 0805; AGILE_PN: 370-76461; CAD_APPROVED: Yes; HEIGHT: 0.9MM; MFG_NAME01: LITE ON; MFG_PN01: LTST-C171KRKT; ROHS: Yes
LED5 = LED: LED BLUE SGL 20MA SMT 0805; AGILE_PN: 370-76451; CAD_APPROVED: Yes; HEIGHT: 0.9MM; MFG_NAME01: LITE ON; MFG_PN01: LTST-C171TBKT; ROHS: Yes
LED6 = LED: LED GRN SGL 30MA SMT 0805; AGILE_PN: 370-76462; CAD_APPROVED: Yes; HEIGHT: 0.9MM; MFG_NAME01: LITE ON; MFG_PN01: LTST-C171KGKT; ROHS: Yes
Q1 Q2 = NPN: TRAN NPN GEN 200MA 40V SOT-23; AGILE_PN: 480-75173; CAD_APPROVED: Yes; HEIGHT: 1.12 MM; MFG_NAME01: ON SEMICONDUCTOR; ROHS: Yes
R12 = RES: RES MF 4.7K 1/16W 5% 0402; AGILE_PN: 470-75626; CAD_APPROVED: Yes; FPLIST: RC0402_25,RC0402_HD,0402_CC; MFG_NAME01: YAGEO AMERICA; MFG_PN01: RC0402JR-074K7L; ROHS: Yes; Tolerance: 5%
R14 = RES: RES MF 47K 1/16W 5% 0402; AGILE_PN: 470-75559; CAD_APPROVED: Yes; FPLIST: RC0402_25,RC0402_HD,0402_CC; MFG_NAME01: VENKEL COMPANY; MFG_PN01: CR0402-16W-473JT; ROHS: Yes; Tolerance: 5%
R17 R26 R510 R513 = RES: RES MF 10.0K 1/16W 1% AEC-Q200 0402; AGILE_PN: 470-75416; ASSY_OPT: DNP; CAD_APPROVED: Yes; FPLIST: RC0402_25,RC0402_HD,0402_CC; HEIGHT: 0.4MM; MFG_NAME01: VISHAY INTERTECHNOLOGY; MFG_PN01: CRCW040210K0FKED; PRIORITY_PN: 006-00552; ROHS: Yes; TOL: 1%; Tolerance: 1%
R45 R54 R87 R88 = RES: RES MF ZERO OHM 1/10W -- AEC-Q200 0603; AGILE_PN: 470-75407; CAD_APPROVED: Yes; FPLIST: RC0603_OV,RC0603,R603-X2,0603_CC; MFG_NAME01: VISHAY INTERTECHNOLOGY; MFG_PN01: CRCW06030000Z0EA; ROHS: Yes; Tolerance: 1%
R48 R53 R57 R62 R81 R511 = RES: RES MF 330 OHM 1/16W 5% 0402; AGILE_PN: 470-75613; CAD_APPROVED: Yes; FPLIST: RC0402_25,RC0402_HD,0402_CC; MFG_NAME01: VISHAY INTERTECHNOLOGY; MFG_PN01: CRCW0402330RJNED; ROHS: Yes; Tolerance: 5%
R67 = POT: RES POT 5K 1/2W 20% TH; AGILE_PN: 470-80115; CAD_APPROVED: Yes; MFG_NAME01: BOURNS; MFG_PN01: 3352T-1-502LF; ROHS: Yes; Tolerance: 20%
R79 = RES: RES MF 27K 1/16W 5% 0402; AGILE_PN: 470-76069; CAD_APPROVED: Yes; FPLIST: RC0402_25,RC0402_HD,0402_CC; MFG_NAME01: VISHAY INTERTECHNOLOGY; MFG_PN01: CRCW040227K0JNED; ROHS: Yes; Tolerance: 5%
R80 = RES: RES MF 1.5K 1/16W 5% 0402; AGILE_PN: 470-76303; CAD_APPROVED: Yes; FPLIST: RC0402_25,RC0402_HD,0402_CC; MFG_NAME01: VISHAY INTERTECHNOLOGY; MFG_PN01: CRCW04021K50JNED; ROHS: Yes; Tolerance: 5%
R82 = RES: RES MF 18.2 OHM 1/4W 1% 0805; AGILE_PN: 470-80116; CAD_APPROVED: Yes; FPLIST: RC0805_OV,RC0805,0805_CC; MFG_NAME01: ROHM; MFG_PN01: ESR10EZPF18R2; ROHS: Yes; Tolerance: 1%
SH3 SH4 SH7-SH15 SH20-SH31 SH33 = RES_SHORT-2: ZERO OHM CUT TRACE 0402 PADS; NO PART TO ORDER; AGILE_PN: 470-76449; CAD_APPROVED: Yes; FPLIST: SH0402,SH0402_CC; MFG_NAME01: LAYOUT ELEMENT ONLY; MFG_PN01: LAYOUT ELEMENT ONLY; ROHS: Yes
SW1 SW2 = ELECTRODE: CAPACITIVE SINGLE ELECTRODE 3X3MM SQUARED ROUNDED CORNERS (NOT A PART TO ORDER); AGILE_PN: 510-77018; CAD_APPROVED: Yes; HEIGHT: 0MM; MFG_NAME01: Freescale; MFG_PN01: Single Electrode 3MM x 3MM; ROHS: Yes
TP31 = TESTLOOP: TEST POINT PC MULTI PURPOSE BLK TH; AGILE_PN: 210-79450; CAD_APPROVED: Yes; HEIGHT: 8.13MM; MFG_NAME01: KEYSTONE ELECTRONICS; MFG_PN01: 5011; ROHS: Yes
TP540-TP543 = TestLoop: TEST POINT PAD 30MIL DIA SMT, NO PART TO ORDER; AGILE_PN: 211-76642; CAD_APPROVED: Yes; HEIGHT: 0.1MM; MFG_NAME01: NOTACOMPONENT; MFG_PN01: NOTACOMPONENT; ROHS: Yes
TVS1 TVS2 = DIODE_TVS_BIDIR: DIODE ESD SUPPRESSOR BIDIR -- 12V 0402; AGILE_PN: 480-78091; ASSY_OPT: DNP; CAD_APPROVED: Yes; HEIGHT: 0.38MM; MFG_NAME01: LITTELFUSE; ROHS: Yes
U4 = AT45DB021E_9P: IC MEM SPI SERIAL 2MBIT FLASH 85MHZ 1.65-3.6V UDFN8; AGILE_PN: 342-00586; CAD_APPROVED: Yes; HEIGHT: 0.6MM; MFG_NAME01: Adesto Technologies Corporation, Inc; MFG_PN01: AT45DB021E-MHN2B-T; ROHS: Yes
U9 = FXOS8700CQ_QFN_16P: IC ACCELEROMETER AND MAGNETOMETER SENSOR 3-AXIS 2.5V QFN16; AGILE_PN: TMP-WF-16648; CAD_APPROVED: Yes; HEIGHT: 1.25MM; MFG_NAME01: Freescale Semiconductor; PRE_APN: 312-80418; ROHS: Yes
U12 = TXB0104: IC VXLTR 4BIT BIDIRECTIONAL 1.2-3.6V/1.65-5.5V QFN14; HEIGHT: 1MM; MFG_NAME01: TEXAS INSTRUMENTS; MFG_PN01: TXB0104RGYR; ROHS: Yes
Y2 = CRYSTAL: XTAL 32.768KHZ SMT ROHS COMPLIANT; AGILE_PN: 230-76374; CAD_APPROVED: Yes; HEIGHT: 0.9MM; MFG_NAME01: EPSON ELECTRONICS; MFG_PN01: FC-135 32.7680KA-A3; ROHS: Yes

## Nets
GND: ANT1.2(GND) BT500.3(neg) C1.2 C2.2 C3.2 C6.2 C9.2 C10.2 C11.2 C15.2 C21.2 C22.2 C25.2 C27.2 C31.2 C32.2 C33.2 C39.2 C41.2 C43.2 C44.2 C45.2 C46.2 C47.2 C48.2 C49.2 C50.2 C51.2 C52.2 C53.2 C54.2 C55.2 C500.2 C501.2 C502.2 C503.2 C504.2 C505.2 C506.2 C507.2 C508.2 C509.2 C510.2 C511.2 C512.2 C513.2 C514.2 C515.2 C516.2 C517.2 C518.2 C519.2 C520.2 C521.2 C522.2 C523.2 C524.2 C525.2 C526.2 C527.2 C528.2 C529.2 C530.2 C531.2 J2.14(B7) J3.12(B6) J3.14(B7) J5.2(SHIELD2) J5.3(SHIELD1) J5.4(SHIELD3) J5.5(SHIELD4) J6.5(GND) J9.3(A2) J9.5(A3) J11.3(A2) J11.5(A3) J16.2(B1) J17.2(B1) J19.2 J26.2 L2.2 L4.2 Q1.2(EMITTER) Q2.2(EMITTER) R14.2 R23.2 R39.2 R44.2 R47.2 R51.2 R60.2 R65.2 R67.3(B) R79.2 R81.2 R85.2 R505.2 R506.2 SH18.2 SH19.2 SW3.2(S2) SW4.2(S2) SW6.1(S1) TP2.1(Pin1) TP22.1(Pin1) TP31.1(Pin1) TP36.1(Pin1) TVS1.2(A2) TVS2.2(A2) U1.2(A2) U2.2(A2) U4.7(GND) U4.9(EP) U5.2(GND) U6.2(A2) U7.2(VSS1) U7.8(VSSA) U7.33(EPAD) U8.3(DIR) U8.4(GND) U9.3(RSVD1) U9.5(GND1) U9.12(GND2) U9.13(RSVD2) U10.2(GND) U11.2(GND) U12.7(GND) U12.15(EXP) U13.2(GND) U14.2(GND) U15.2(GND) U16.2(GND) U17.1(GND) U18.13(DCDC_GND) U18.26(VSSA) U18.49(GND1) U18.50(GND2) U18.51(GND3) U18.52(GND4) U18.53(GND5) U18.54(GND6) U18.55(GND7) U18.56(GND8) U18.57(GND9) U18.58(GND10) U18.59(GND11) U18.60(GND12) U18.61(GND13) U18.62(GND14) U18.63(GND15) U18.64(GND16) U500.4(GND) X1.2 Y1.2 Y1.4 Z1.2(GND/DC_FEED) Z1.5(GND)
P3V3: C48.1 C510.1 J3.4(B2) J3.8(B4) J8.1 J9.1(A1) J15.1 J18.2(B1) J20.1 J21.1 R17.1 R26.1 R78.1 R508.1 R509.1 SH3.1 SH500.2 SH502.2 SH503.2 TP534.1(Pin1) U12.1(VCCA) U12.8(OE)
P3V3_BATT: BT500.1(pos1) BT500.2(pos2) C43.1 J27.2
P3V3_BRD: C6.1 C507.1 C508.1 C519.1 J8.2 R13.1 R16.1 R20.1 R22.2 R24.1 R29.1 R507.1 R510.1 R513.1 TP518.1(Pin1) U4.6(VCC) U9.1(VDDIO) U9.14(VDD)
P3V3_LED: C49.1 LED1.A(ANODE) LED2.A(ANODE) LED3.A(ANODE) LED4.A(ANODE) LED5.A(ANODE) R82.1 SH503.1 TP544.1(Pin1)
P3V3_LED_PWR: J20.2 LED6.A(ANODE) TP536.1(Pin1)
P3V3_SDA: C31.1 C501.1 C502.1 C504.1 C505.1 C509.1 C513.1 C514.1 C516.1 C518.1 C521.1 C523.1 J11.1(A1) R10.1 R19.1 R33.1 R34.2 R37.1 R38.1 R49.1 R59.1 R63.1 R64.1 R501.2 R503.1 SH501.1 U5.1(VCCA) U7.1(VDD1) U7.7(VDDA) U7.11(VBAT) U8.7(VCCA) U11.5(VCC) U13.1(VCCA) U14.1(VCCA) U15.1(VCCA) U16.1(VCCA) U500.1(VCCA)
P3V3_VREG: C27.1 D7.A U17.2(VOUT) U17.4(TAB)
P5V0_SDA_USB_CONN_VBUS: J6.1(VBUS) L1.1 TP513.1(Pin1) U6.1(A1)
P5V_LDO_OUT: C53.1 D10.A J26.3
P5V_SDA: C3.1 C13.1 C21.1 L1.2 R40.1 R46.1 R504.1 U7.6(VREGIN) U10.1(VIN)
P5V_SDA_PSW: D3.A D4.A U10.6(VOUT)
P5V_USB: C512.1 D4.C D5.A D10.C J3.10(B5) U12.14(VCCB)
VDD_1P8: J22.5(A3) U18.14(VDD_1P8)
VDD_1P8F: C55.1 L5.2 U18.27(VREFH) U18.28(VDDA)
VDD_1P45: C45.1 L6.1 U18.15(VDD_1P45)
VDD_1P45F: C54.1 C525.1 C526.1 C527.1 J22.4(B2) L6.2 U18.31(VDD_XTAL) U18.32(VDD_RF2) U18.35(VDD_RF1)
ADC0_SE0/BATTERY_MONITORING: R78.2 SH26.1 U18.24(ADC0_DP0/CMP0_IN0)
ADC0_SE1/POT: C32.1 R67.2(WIPER) SH27.1 TP532.1(Pin1) U18.25(ADC0_DM0/CMP0_IN1)
BUZZER: R12.1 SH10.1 SH22.2 U18.19(PTB3/ADC0_SE2/CMP0_IN4/CLKOUT/TPM1_CH1/RTC_CLKOUT/ERCLK32K)
BYP_FXOS8700CQ: C22.1 U9.2(BYP)
CMT: R80.1 SH29.1 TP535.1(Pin1) U18.17(PTB1/ADC0_SE1/CMP0_IN5/I2C0_SDA/LPTMR0_ALT1/TPM0_CH2/CMT_IRO)
COM: R511.2 SH31.1 U18.16(PTB0/I2C0_SCL/CMP0_OUT/TPM0_CH1/CLKOUT)
CRST_FXOS8700CQ: C11.1 U9.8(CRST)
D7: R5.1 U12.10(B4)
D8: R4.1 U12.11(B3)
D9: R3.1 U12.12(B2)
D10: R8.1 U12.13(B1)
DCDC_CFG: J17.1(A1) J17.3(A2) U18.9(DCDC_CFG)
DCDC_LP: J17.5(A3) L3.1 U18.11(DCDC_LP)
ELEC_IN1: SH15.1 SW2.1 TVS1.1(A1) U18.4(PTA16/TSI0_CH10/SPI1_SOUT/TPM0_CH0)
ELEC_IN2: SH14.1 SW1.1 TVS2.1(A1) U18.5(PTA17/TSI0_CH11/SPI1_SIN/TPM_CLKIN1)
EXTAL_32M: C44.1 U18.29(EXTAL_32M) Y1.1
I2C1_SCL: R42.2 R54.2 R509.2 TP20.1(Pin1) U18.38(PTC2/TSI0_CH14/TX_SWITCH/I2C1_SCL/UART0_RX/CMT_IRO/DTM_RX)
I2C1_SDA: R30.2 R45.1 R508.2 TP19.1(Pin1) U18.39(PTC3/TSI0_CH15/RX_SWITCH/I2C1_SDA/UART0_TX/DTM_TX)
I2C_SCL_FXOS8700CQ: R42.1 U9.4(SCL/SCLK)
I2C_SDA_FXOS8700CQ: R30.1 U9.6(SDA/MOSI)
INT1_COMBO: R7.2 R68.2 R510.2 SH11.1
INT1_COMBO_R: R7.1 U9.11(INT1)
INT2_COMBO: R18.2 R513.2 TP14.1(Pin1)
INT2_COMBO_R: R18.1 U9.9(INT2)
J_VDD_1P8F: C39.1 C524.1 C528.1 C529.1 C530.1 J18.4(B2) J22.3(A2) L5.1 U18.20(VDD_0) U18.44(VDD_1/VDD)
KW40_SWD_CLK: J12.2 SH8.1 TP506.1(Pin1) U18.2(PTA1/SWD_CLK/TSI0_CH9/TPM1_CH1)
LVLRST_EN: R501.1 U500.5(OE)
MIC2005_CSLEW: C13.2 U10.5(CSLEW)
P5-9V_VIN: C50.1 C51.1 C52.1 D6.A J3.16(B8) J26.1
P5-9V_VIN_VR: D3.C D5.C D6.C J33.2
POWER_EN: R41.1 U7.31(ADC0_SE7B/PTD6/SPI0_PCS3/UART0_RX/FTM0_CH6/FTM0_FLT0/LLWU_P15)
PSWITCH: J16.1(A1) J16.3(A2) J16.5(A3) SW5.1(S1) U18.8(PSWITCH)
PTB16: R71.1 SH28.1
PTB16/XTAL_32K: R71.2 R74.1 U18.21(PTB16/EXTAL32K/I2C1_SCL/TPM2_CH0)
PTB17: R76.2 SH25.1
PTB17/EXTAL_32K: R76.1 R77.1 U18.22(PTB17/XTAL32K/I2C1_SDA/TPM2_CH1)
PTB18: SH33.1 U18.23(PTB18/DAC0_OUT/ADC0_SE4/CMP0_IN2/I2C1_SCL/TPM_CLKIN0/TPM0_CH0/~{NMI})
PTC0: R62.2 R88.2 TP542.1(Pin1) U18.36(PTC0/ANT_A/I2C0_SCL/~{UART0_CTS}/TPM0_CH1)
PTC1: R57.2 R87.1 TP540.1(Pin1) U18.37(PTC1/ANT_B/I2C0_SDA/~{UART0_RTS}/TPM0_CH2/BLE_ACTIVE)
PTC4: R53.2 R56.2 SH20.2 SH24.1 TP543.1(Pin1) U18.40(PTC4/TSI0_CH0/EXTRG_IN/~{UART0_CTS}/TPM1_CH0)
PTC5: R48.2 R52.2 SH23.2 SH30.1 TP541.1(Pin1) U18.41(PTC5/TSI0_CH1/LPTMR0_ALT2/~{UART0_RTS}/TPM1_CH1)
RF_50: C33.1 C34.1 C40.1 L4.1 Z1.1(UNBAL)
RF_ANT: ANT1.1(Signal) C40.2
RF_N: R70.1 U18.33(RF_N)
RF_P: R69.1 U18.34(RF_P)
RF_SMA: C34.2 J5.1(CENTER)
RST_FXOS8700CQ: R32.1 R506.1 U9.16(RST)
RST_TGTMCU_b: D1.C(CATHODE) J3.6(B3) J9.10(B5) J24.3 R32.2 R500.2 R502.2 TP519.1(Pin1) U18.3(PTA2/~{RESET}/TMP0_CH3) U500.7(B1)
SA0_FXOS8700CQ: R29.2 SH19.1 U9.7(SA0/MISO)
SA1_FXOS8700CQ: R13.2 SH18.1 U9.10(SA1/~{CS})
SDA_CTS_EN: R37.2 R39.1 U13.5(DIR)
SDA_EXTAL: C15.1 U7.17(EXTAL0/PTA18/FTM0_FLT2/FTM_CLKIN0) X1.3
SDA_JTAG_TCLK: J11.4(B2) U7.12(JTAG_TCLK/SWD_CLK/EZP_CLK/TSI0_CH1/PTA0/~{UART0_CTS}/~{UART0_COL}/FTM0_CH5)
SDA_JTAG_TDI: J11.8(B4) U7.13(JTAG_TDI/EZP_DI/TSI0_CH2/PTA1/UART0_RX/FTM0_CH6)
SDA_JTAG_TDO: J11.6(B3) U7.14(JTAG_TDO/TRACE_SWO/EZP_DO/TSI0_CH3/PTA2/UART0_TX/FTM0_CH7)
SDA_JTAG_TMS: J11.2(B1) R63.2 U7.15(JTAG_TMS/SWD_DIO/TSI0_CH4/PTA3/~{UART0_RTS}/FTM0_CH0)
SDA_LED: D2.C(CATHODE) TP507.1(Pin1) U7.29(PTD4/SPI0_PCS1/~{UART0_RTS}/FTM0_CH4/EWM_IN/LLWU_P14)
SDA_LED_R: D2.A(ANODE) R10.2
SDA_RST: J11.10(B5) R46.2 R47.1 TP524.1(Pin1) U7.19(~{RESET})
SDA_RST_LED: D1.A(ANODE) R1.2
SDA_RST_TGTMCU_B: J25.2 U7.21(ADC0_SE9/TSI0_CH6/PTB1/I2C0_SDA/FTM1_CH1/FTM1_QD_PHB)
SDA_RST_TGTMCU_J_B: J24.1 J25.1 R502.1 R503.2 U500.2(A1)
SDA_RTS_EN: R49.2 R51.1 U14.5(DIR)
SDA_RX_EN: R19.2 R23.1 U5.5(DIR)
SDA_SPI0_SCK: TP529.1(Pin1) U7.26(PTC5/SPI0_SCK/LPTMR0_ALT2/I2S0_RXD0/CMP0_OUT/LLWU_P9) U16.3(A)
SDA_SPI0_SIN: TP515.1(Pin1) U7.28(CMP0_IN1/PTC7/SPI0_SIN/USB_SOF_OUT/I2S0_RX_FS) U8.5(2A)
SDA_SPI0_SOUT: TP528.1(Pin1) U7.27(CMP0_IN0/PTC6/SPI0_SOUT/PDB0_EXTRG/I2S0_RX_BCLK/I2S0_MCLK/LLWU_P10) U15.3(A)
SDA_SWD_EN: R50.1 R66.1 U11.6(~{Y2})
SDA_SWD_EN_B: R31.2 U7.16(~{NMI}/~{EZP_CS}/TSI0_CH5/PTA4/FTM0_CH1/LLWU_P3)
SDA_SWD_EN_B_R: R31.1 R38.2 U11.1(A1)
SDA_SWD_EN_R: R64.2 R65.1 R66.2 U16.5(DIR)
SDA_SWD_OE: R36.1 R61.1 U11.4(~{Y1})
SDA_SWD_OE_B: R35.2 U7.20(ADC0_SE8/TSI0_CH0/PTB0/I2C0_SCL/FTM1_CH0/FTM1_QD_PHA/LLWU_P5)
SDA_SWD_OE_B_R: R34.1 R35.1 U11.3(A2)
SDA_SWD_OE_R: R59.2 R60.1 R61.2 U15.5(DIR)
SDA_USB_DN: R25.2 U7.4(USB0_DM)
SDA_USB_DP: R21.2 U7.3(USB0_DP)
SDA_USB_P5V_SENSE: R504.2 R505.1 TP510.1(Pin1) U7.30(ADC0_SE6B/PTD5/SPI0_PCS2/~{UART0_CTS}/~{UART0_COL}/FTM0_CH5/~{EWM_OUT})
SDA_VOUT33: C506.1 SH501.2 SH502.1 U7.5(VOUT33)
SDA_XTAL: C10.1 U7.18(XTAL0/PTA19/FTM1_FLT0/FTM_CLKIN1/LPTMR0_ALT1) X1.1
SPI_CLK: R16.2 SH4.1 TP504.1(Pin1) U4.2(SCK) U18.45(PTC16/TSI0_CH4/SPI0_SCK/I2C0_SDA/~{UART0_RTS}/TPM0_CH3)
SPI_SIN: J28.2 R84.2 TP508.1(Pin1) U4.8(SO)
SPI_SOUT: J29.1 R83.2 TP509.1(Pin1) U4.1(SI)
SPI_SS: R24.2 SH7.1 TP516.1(Pin1) U4.4(~{CS}) U18.48(PTC19/TSI0_CH7/SPI0_PCS0/I2C0_SCL/~{UART0_CTS}/BLE_ACTIVE)
SW1_RST_B: C1.1 J24.2 SW6.2(S2)
SW3: C9.1 R26.2 SH12.1 SW3.1(S1) TP503.1(Pin1) U18.7(PTA19/TSI0_CH13/SPI1_PCS0/TPM2_CH1)
SW4: C2.1 R17.2 SH13.1 SW4.1(S1) TP502.1(Pin1) U18.6(PTA18/TSI0_CH12/SPI1_SCK/TPM2_CH0)
SWD_CLK_TGTMCU: J9.4(B2) J12.1 J14.2 TP523.1(Pin1)
SWD_CLK_TGTMCU_BUF: J14.1 U16.4(B)
SWD_DIO_TGTMCU: J9.2(B1) J13.2 SH9.1 SH21.2 TP505.1(Pin1) U18.1(PTA0/SWD_DIO/TSI0_CH8/SPI0_PCS1/TPM1_CH0)
SWD_DIO_TGTMCU_BUF: J13.1 U8.2(2B) U15.4(B)
TC_EXTAL_TP: TP521.1(Pin1) U7.10(EXTAL32)
TC_XTAL_TP: TP520.1(Pin1) U7.9(XTAL32)
TP_2102_A: TP501.1(Pin1) U500.3(A2)
TP_2102_B: TP500.1(Pin1) U500.6(B2)
UART0_CTS_TGTMCU: R43.2 R52.1
UART0_RTS_TGTMCU: R55.2 R56.1
UART0_RX_TGTMCU: J30.2 R27.2 U18.42(PTC6/TSI0_CH2/I2C1_SCL/UART0_RX/TPM2_CH0)
UART0_TX_TGTMCU: J31.1 R28.2 U18.43(PTC7/TSI0_CH3/SPI0_PCS2/I2C1_SDA/UART0_TX/TPM2_CH1)
UART1_CTS_TGTMCU_BUF: R43.1 U13.4(B)
UART1_CTS_TGTMCU_R: R36.2 TP522.1(Pin1) U7.23(ADC0_SE4B/CMP1_IN0/TSI0_CH15/PTC2/SPI0_PCS2/~{UART1_CTS}/FTM0_CH1/I2S0_TX_FS) U13.3(A)
UART1_RTS_TGTMCU_BUF: R55.1 U14.4(B)
UART1_RTS_TGTMCU_R: R50.2 TP525.1(Pin1) U7.22(ADC0_SE15/TSI0_CH14/PTC1/SPI0_PCS3/~{UART1_RTS}/FTM0_CH0/I2S0_TXD0/LLWU_P6) U14.3(A)
UART1_RX_TGTMCU_BUF: R27.1 U5.4(B)
UART1_RX_TGTMCU_R: TP514.1(Pin1) U5.3(A) U7.25(PTC4/SPI0_PCS0/UART1_TX/FTM0_CH3/CMP1_OUT/LLWU_P8)
UART1_TX_TGTMCU_BUF: R28.1 U8.1(1B)
UART1_TX_TGTMCU_R: TP517.1(Pin1) U7.24(CMP1_IN1/PTC3/SPI0_PCS1/UART1_RX/FTM0_CH2/I2S0_TX_BCLK/LLWU_P7) U8.6(1A)
V_BATT: D7.C D8.C J15.3 J18.1(A1) R72.1 R73.2 R75.2 TP30.1(Pin1)
V_MCU: J21.2 J22.1(A1) J22.2(B1) TP533.1(Pin1)
V_TGTMCU: C500.1 C503.1 C511.1 C515.1 C517.1 C520.1 C522.1 R1.1 R500.1 SH500.1 U5.6(VCCB) U8.8(VCCB) U13.6(VCCB) U14.6(VCCB) U15.6(VCCB) U16.6(VCCB) U500.8(VCCB)
VDCDC_IN: C531.1 J16.4(B2) J17.4(B2) J17.6(B3) R72.2 SW5.2(S2) U18.10(VDCDC_IN)
VTRG_EN: R40.2 R41.2 R44.1 U10.3(ENABLE)
VTRG_FAULT_B: R33.2 TP511.1(Pin1) U7.32(PTD7/CMT_IRO/UART0_TX/FTM0_CH7/FTM0_FLT1) U10.4(~{FAULT})
XTAL_32M: C41.1 U18.30(XTAL_32M) Y1.3
N20064946: J3.2(B1) SH24.2
N20065027: J4.11(A6) SH33.2
N20065031: J4.9(A5) SH31.2
N20065043: J4.3(A2) SH27.2
N20065047: J4.1(A1) SH26.2
N20092069: J1.16(B8) R5.2 SH10.2
N20092076: J1.14(B7) SH11.2
N20092083: J1.12(B6) SH12.2
N20092090: J1.10(B5) SH13.2
N20092097: J1.8(B4) SH14.2
N20092104: J1.6(B3) SH15.2
N20092111: J1.4(B2) J31.2
N20092118: J1.2(B1) J30.1
N20113921: J2.6(B3) R8.2 SH7.2
N20113927: J2.12(B6) SH4.2
N20113929: J2.8(B4) J28.1
N20113931: J2.10(B5) J29.2
N20113933: J2.4(B2) R3.2 SH8.2
N20113935: J2.2(B1) R4.2 SH9.2
N20114060: J2.16(B8) SH3.2
N20114116: J2.18(B9) R87.2
N20184312: J4.2(B1) SH25.2
N20184318: J4.4(B2) SH28.2
N20184324: J4.6(B3) SH29.2
N20184330: J4.8(B4) SH30.2
N20184336: J4.10(B5) R45.2
N20184342: J4.12(B6) R54.1
N20299169: J6.2(D-) R25.1 TP4.1(Pin1) U2.1(A1)
N20299247: J6.3(D+) R21.1 TP3.1(Pin1) U1.1(A1)
N20456851: R20.2 U4.3(~{RESET})
N20492386: J2.20(B10) R88.1
N20531142: LED5.C(CATHODE) R511.1 TP531.1(Pin1)
N20531179: LED6.C(CATHODE) R81.1 TP537.1(Pin1)
N20532222: C46.1 R74.2 Y2.1
N20532224: C47.1 R77.2 Y2.2
N20553853: LED4.C(CATHODE) R62.1 TP28.1(Pin1)
N20553861: LED2.C(CATHODE) R53.1 TP25.1(Pin1)
N20553879: LED1.C(CATHODE) R48.1 TP21.1(Pin1)
N20553881: LED3.C(CATHODE) R57.1 TP26.1(Pin1)
N20693809: R68.1 U18.18(PTB2/ADC0_SE3/CMP0_IN3/TPM1_CH0)
N20693837: L3.2 U18.12(DCDC_LN)
N20693945: R84.1 U18.47(PTC18/TSI0_CH6/SPI0_SIN/UART0_TX/DTM_TX)
N20693947: R83.1 U18.46(PTC17/TSI0_CH5/SPI0_SOUT/UART0_RX/DTM_RX)
N20694234: C42.2 R70.2 Z1.4(BAL4)
N20694236: C42.1 R69.2 Z1.3(BAL3)
N20694515: J16.6(B3) R85.1
N20696372: D9.A J19.1
N20696388: D9.C J23.2
N20696455: C25.1 J23.1 J33.1 TP530.1(Pin1) U17.3(VIN)
N20743134: BZ500.2 Q1.3(COLLECTOR) R512.2
N20743140: Q1.1(BASE) R12.2 R14.1
N20743144: BZ500.1 R507.2 R512.1 TP526.1(Pin1)
N20744082: D11.A(ANODE) R82.2 TP538.1(Pin1)
N20744086: Q2.1(BASE) R79.1 R80.2
N20744096: D11.C(CATHODE) Q2.3(COLLECTOR) TP539.1(Pin1)
N20748907: J15.2 R67.1(A)
N20755274: SH22.1 U12.5(A4)
N20755276: SH20.1 U12.3(A2)
N20755278: SH21.1 U12.4(A3)
N20755280: SH23.1 U12.2(A1)
N20771285: J23.3 R75.1
N20771753: D8.A J27.1 R73.1 TP29.1(Pin1)
N20845596: R22.1 U4.5(~{WP})
N20885985: J6.6(SHELL1) J6.7(SHELL2) J6.8(SHELL3) J6.9(SHELL4) J6.10(SHELL5) L2.1

Not connected (* = marked no-connect by the designer): J1 1(A1)* 3(A2)* 5(A3)* 7(A4)* 9(A5)* 11(A6)* 13(A7)* 15(A8)*; J2 1(A1)* 3(A2)* 5(A3)* 7(A4)* 9(A5)* 11(A6)* 13(A7)* 15(A8)* 17(A9)* 19(A10)*; J3 1(A1)* 3(A2)* 5(A3)* 7(A4)* 9(A5)* 11(A6)* 13(A7)* 15(A8)*; J4 5(A3)* 7(A4)*; J6 4(ID); J9 6(B3)* 7(A4)* 8(B4)* 9(A5)*; J11 7(A4)* 9(A5)*; J18 3(A2)*; J22 6(B3)*; U9 15(NC)*; U12 6(NC)* 9(NC1)*; Z1 6(NC)*

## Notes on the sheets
sheet 1
- OpenSDA Interface
- RESET
- 1-2: Default.
  2-3: Reset signal direct to the MCU,
  to use when OpenSDA is not powered.
- RST Push Button
  Bypass
- TARGET MCU
  INTERFACE
  SIGNALS
- Output to system
  from Level shifter
- Output to system
  from Level shifter
- Isolation
  Resistors
- CAD NOTE:
  RX/TX POKA-YOKE:
  Place both
  resistors
  with the same orientation
  and provide same airgap
  between RX to TX resistors
  terminals in a square fashion.
- PU/PD LOGIC:
  SERIAL INTERFACE
  IS ALWAYS RESET
  WHEN USB PORT
  IS DISCONNECTED
- Output to system
  from Level shifter
- SHORTING HEADER
  ON BOTTOM LAYER
- SHORTING HEADER
  ON BOTTOM LAYER
- HW Designer: Rafael del Rey
- Output to system
  from Level shifter
- Output to system
  from Level shifter
- OPEN SDA
  POWER OUTPUTS
- OPEN SDA
  INPUT POWER
- i
- path
- i
- path
- Note: You can power openSDA
  with your own power supplies
  by replacing this rail
  (SDA_VOUT33)
  with your 3.3V power supply rail
- 3.3VDC, 10mA should be provided
  to this rail (P3V3_SDA)
  in order to power openSDA
  module
- Isolation and level shift stage
  (for 1.8 to 5V compatibility)
- PU/PD LOGIC (DIR PIN):
  BUFFER IS TRISTATED WHEN
  P3V3_SDA IS UNPOWERED
- i
- path
- PWR SWITCH
- OpenSDA INTERFACE JTAG CONNECTOR
- (To enable 5v from
  USB connector)
- SDA_VOUT33 can provide up to 120mA
  of power at 3.3VDC to your system
  P5V_TRG_SDA can provide up to 450mA
  (per USB spec) of power at 5VDC
  to your system
- ACTIVE HIGH
- I/O POWER
  INPUT
- i
- path
- This power rail is supported
  from 1.8V to 5V
- Power should be provided
  to this rail for the logic
  related to your platform I/O
- {For enablement purposes only}
sheet 2
- Power Configuration
- DCDC_CFG
- REG_CFG
- PSW_CFG
   J16
- PWR_CFG
   J18
- DCDC_CFG
   J17
- REG_CFG
   J22
- Place caps close to DUT
- 1-3
- Bypass (1.8V - 3.6V)
- 1-2
- 1-2
- 3-4
- 2-4
- PSW_CFG
- Buck (1.8V - 4.2V)
  - Coin Cell
- 2-4
- 5-6
- 3-4
- 3-5
- Boost Auto Mode
  (1.8V - 4.2V)
- 2-4
- 3-4
- 3-4
- 3-5
- Boost (0.9V - 1.8V)
  - Single battery
- 2-4
- 3-4
- 1-2
- 3-5
- 5-6
- (1.45-3.6V)
- (1.71-3.6V)
- UART FlowControl
- CAD NOTE:
  Embed pads into
  50 Ohm line.
- 100 Ohm controlled
  impedance from DUT
  to balun.
- CAD NOTE:
  SMA - F-Antenna:
  Place both
  capacitor
  sharing pin 1
- Place ind close to DUT
- HARMONIC TRAP
- RF
- CAD NOTE:
  Open Solder Mask
  Bottom below
  F-Antenna on
  "feedpoint" via
- 50 ohm controlled
  impedence line from
  Balun to SMA and F_Antenna
- MKW40Z160 MCU
- POWER MANAGMENT
- SWD CONNECTOR
- SHORTING HEADER ON BOTTOM LAYER
  Jumper is shorted by a cut-trace
  on bottom layer. Cutting the trace
  will effectively isolate the on-board
  MCU from the OpenSDA
  debug interface.
- PWR_CFG
- COIN CELL
  HOLDER
- * For External PS, If 3.6V - 20V shunt J23 1-2,
  else if PS 1.8 - 3.6V shunt J23 2-3.
- BATTERY_MONITOTING
- EXTERNAL PS
- 32MHz XTAL
sheet 3
- 1. Unless Otherwise Specified:
- All resistors are in ohms, 5%, 1/8 Watt
- All capacitors are in uF, 20%, 50V
- All voltages are DC
- All polarized capacitors are aluminum electrolytic
- 2. Interrupted lines coded with the same letter or letter
      combinations are electrically connected.
- 3. Device type number is for reference only. The number
      varies with the manufacturer.
- 4. Special signal usage:
- _B Denotes - Active-Low Signal
- <> or [] Denotes - Vectored Signals
- 5. Interpret diagram in accordance with American
  National Standards Institute specifications, current
  revision, with the exception of logic block symbology.
sheet 4
- Table of Contents
- Revisions & Change Log
- 1
- Title
- Rev
- Description
- Date
- Approved
- 2
- Block Diagram
- X1
- Initial Draft
- 05/9/14
- A. QUIROZ
- 3
- MKW40Z MCU
- DCDC Jumper Sets
  FXOS8700CQ Accel
  RF Balun matching
- X2
- 05/19/14
- A. QUIROZ
- 4
- OpenSDA INTERFACE
- 5
- I/O Headers and Power Supply
- BOM Optimization,
  Adding TP for Testing
- 05/23/14
- A. QUIROZ
- Prototype Release
- A
- 07/08/14
- A. QUIROZ
- Update BOM, SPI Flash
  Memory
- B
- 11/18/14
- A. QUIROZ
- Update RF BOM, Adding
  DCDC capacitor
- B3
- 04/06/15
- A. QUIROZ
- Update headers and
  PokaYokes
- C
- 7/30/15
- FREEDOM KW40Z
       BLE/Zigbee
- SCH-28379 | PDF: SPF-28379
sheet 5
- UART0
- ELECTRODES
- PB
- INTERRUPT PUSH BUTTONS
- 32kHz XTAL
- SPI0
- I2C0
- 2MBit (256KB) FLASH
- PB LED
- CAD NOTE:
  MISO/MOSI POKA-YOKE:
  Place both
  resistors
  with the same orientation
  and provide same airgap
  between MISO to MOSI resistors
  terminals in a square fashion.
- FREEDOM PLATFORM
  COMPATIBILITY HEADERS
- 5VDC VR
  SUPPORT
- USB HOST POWER
- IN
- OUT
- INFRARED LED
- IN CIRCUIT TEST
  GND PROBING
- FXOS8700CQ COMBO SENSOR
- CAD NOTE:
  SCL/SDA POKA-YOKE:
  Place both
  resistors
  with the same orientation
  and provide same airgap
  between SCL to SDA resistors
  terminals in a square fashion.
- I2C1
- ARDUINO COMPATIBLE HEADERS
- DEBUG GROUND
  HOOK
- POWER ON/
  COMMUNICATING
- FRDM-KW40 signals to DEMO which
  require translation from 3.3 V to 5V.
  Zero Ohm 0402 Cut Trace PCB Footprint.
- POT
- BUZZER
